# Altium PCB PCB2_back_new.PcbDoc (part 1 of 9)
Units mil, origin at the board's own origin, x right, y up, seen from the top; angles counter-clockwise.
Board outline 6299 x 3937 mil, 4 copper layers (TopLayer, GROUND, VCC, BottomLayer); 253 components, 421 nets, 2085 pads, 712 vias.
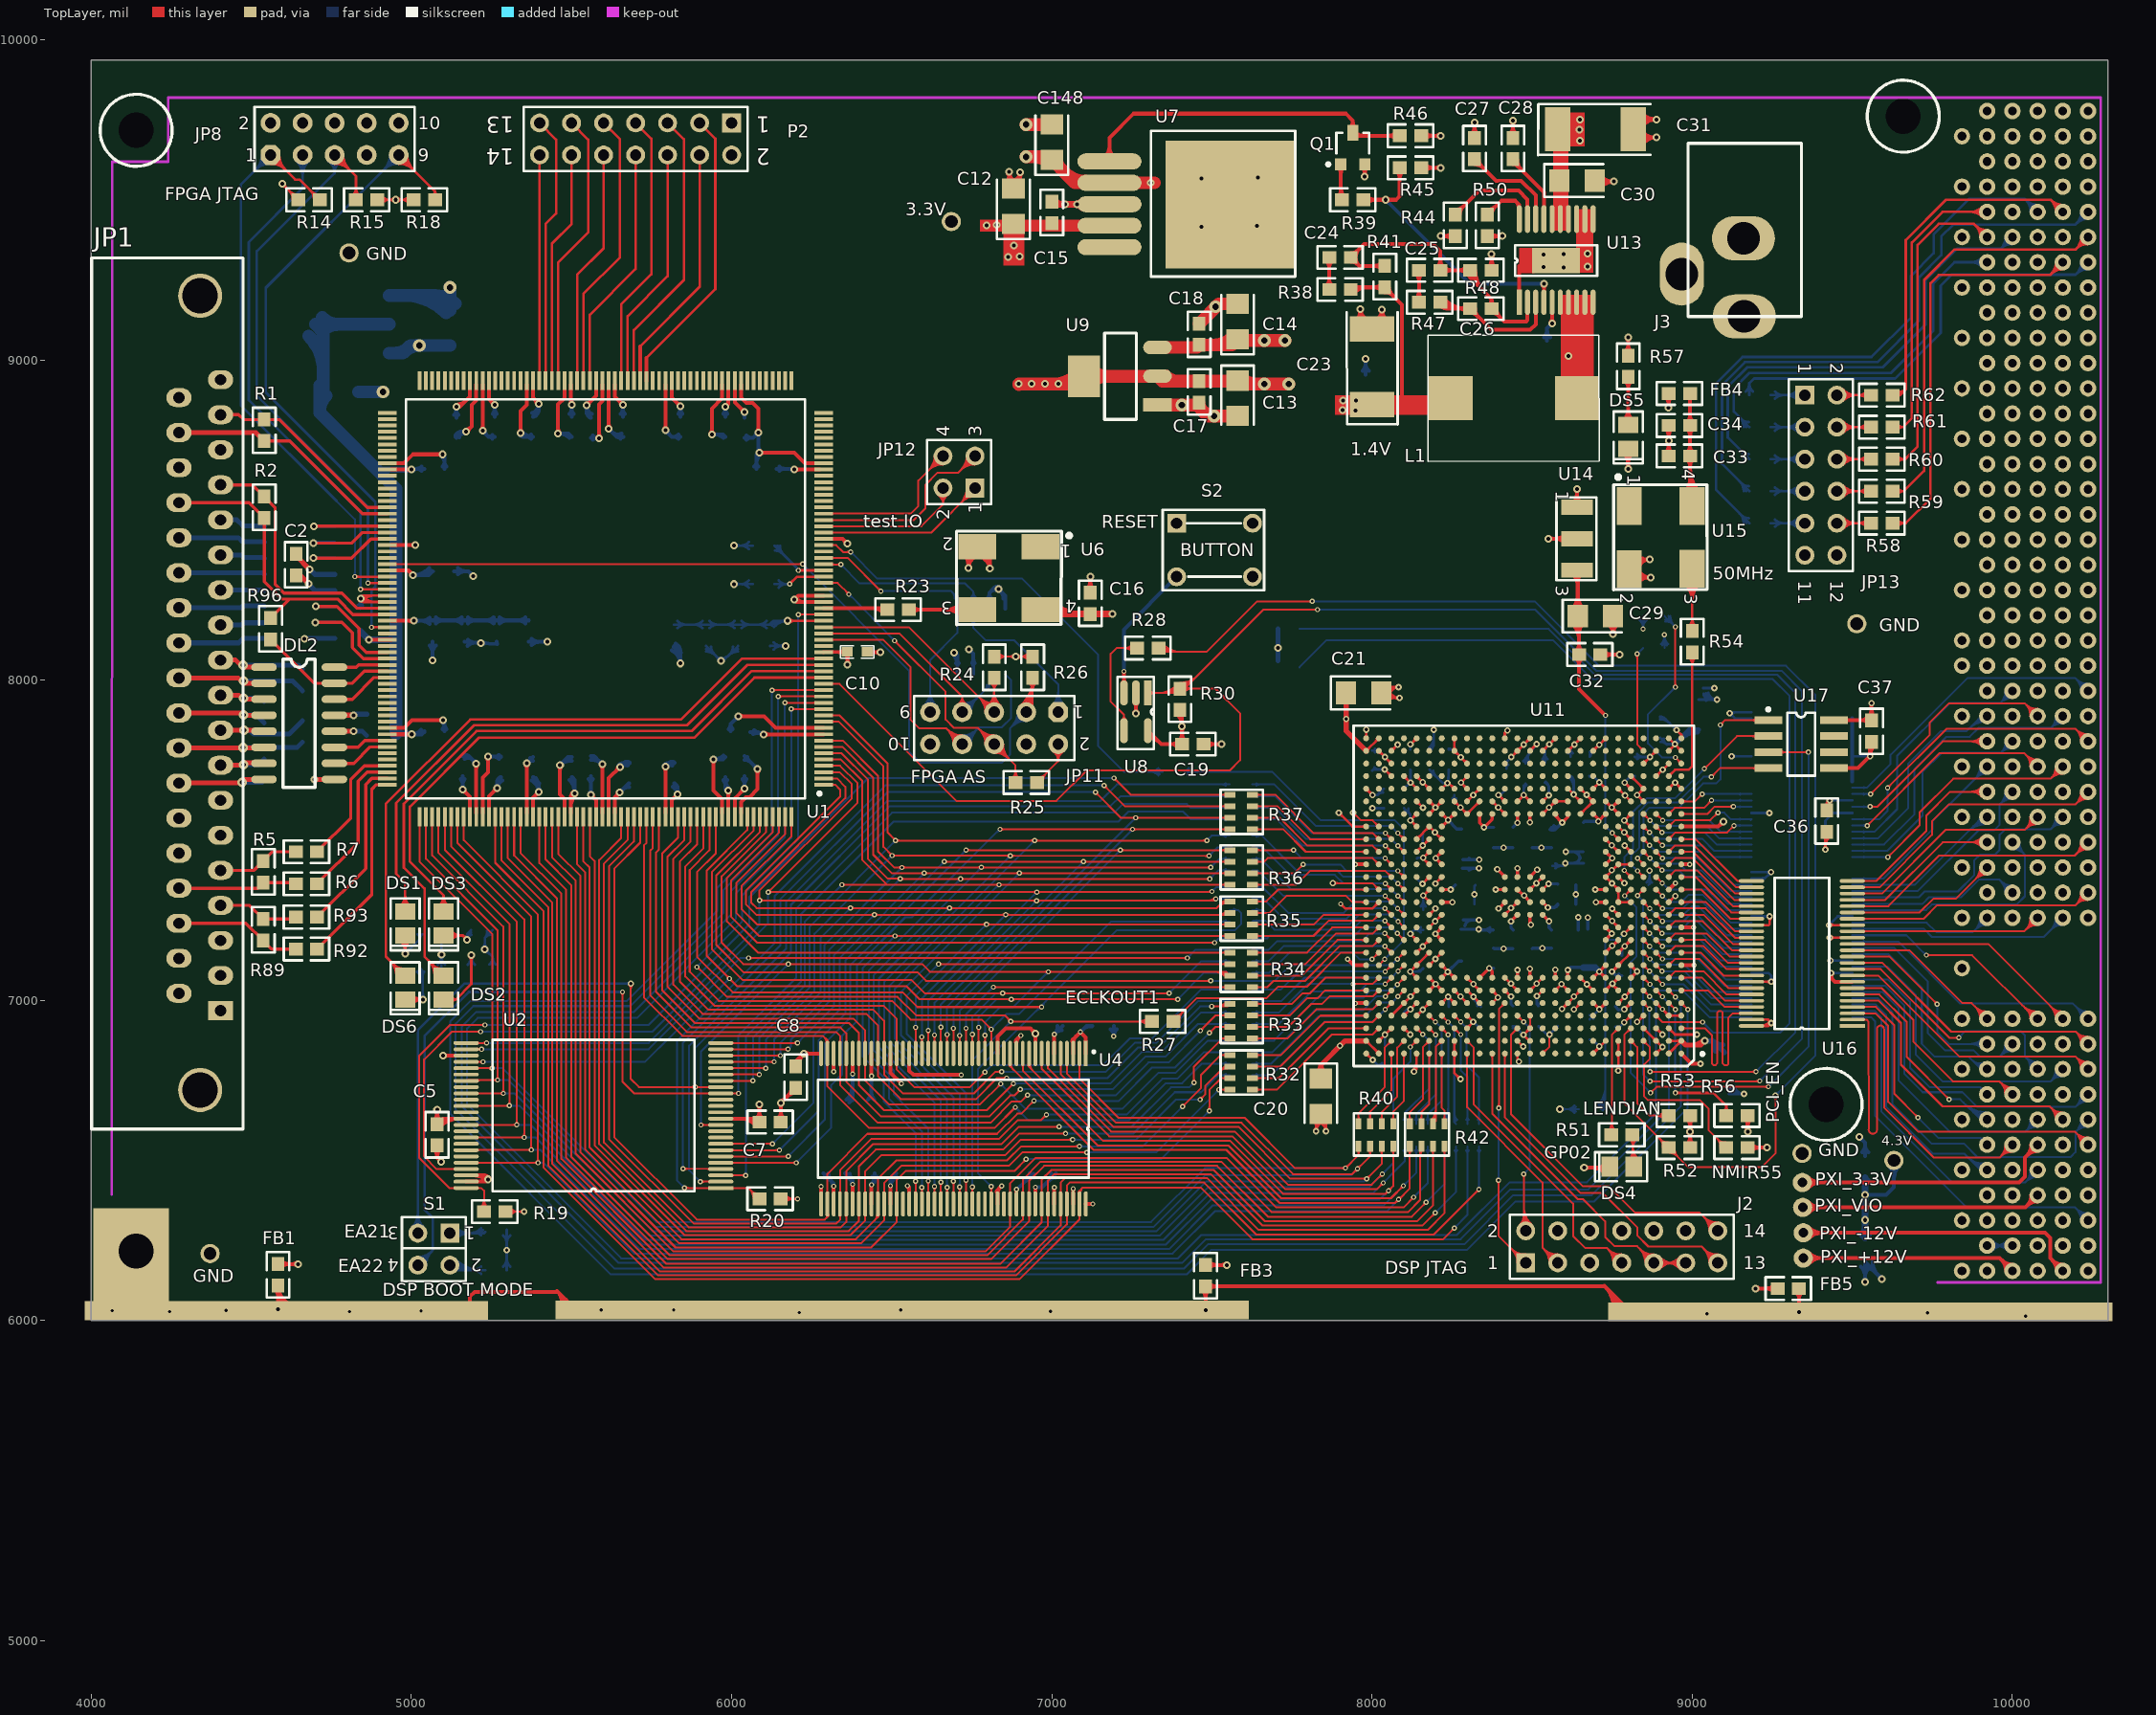
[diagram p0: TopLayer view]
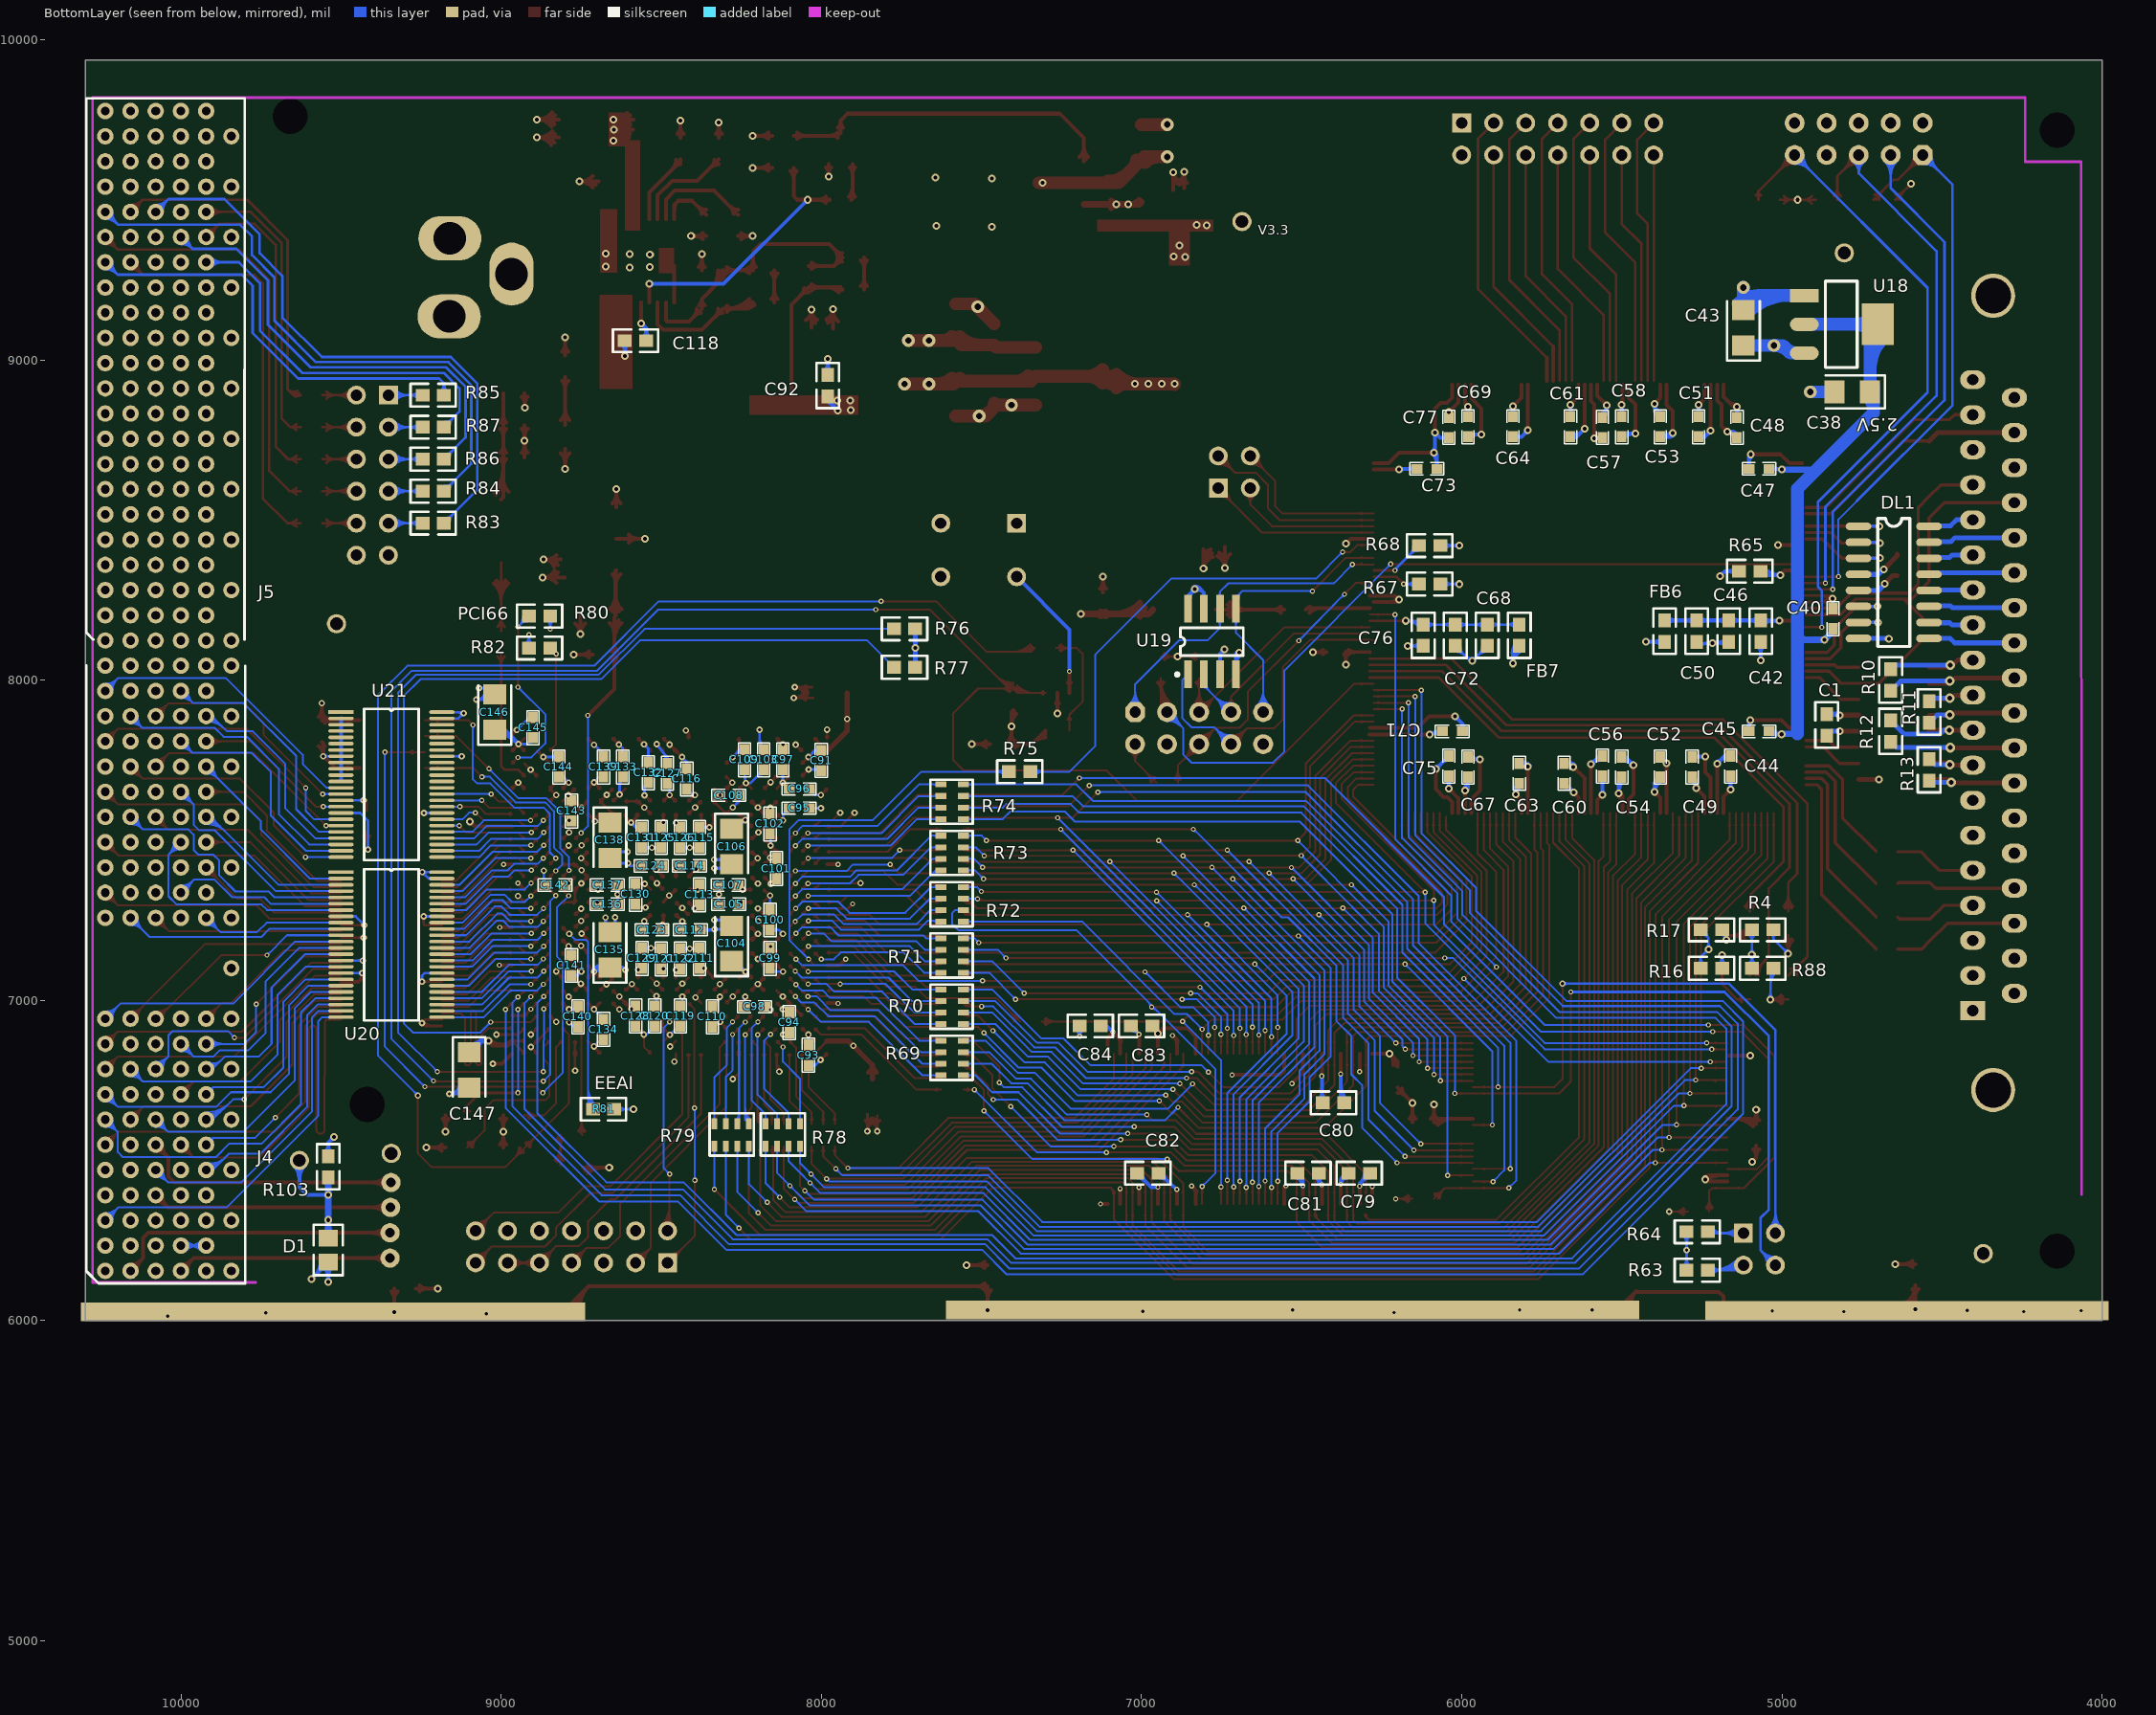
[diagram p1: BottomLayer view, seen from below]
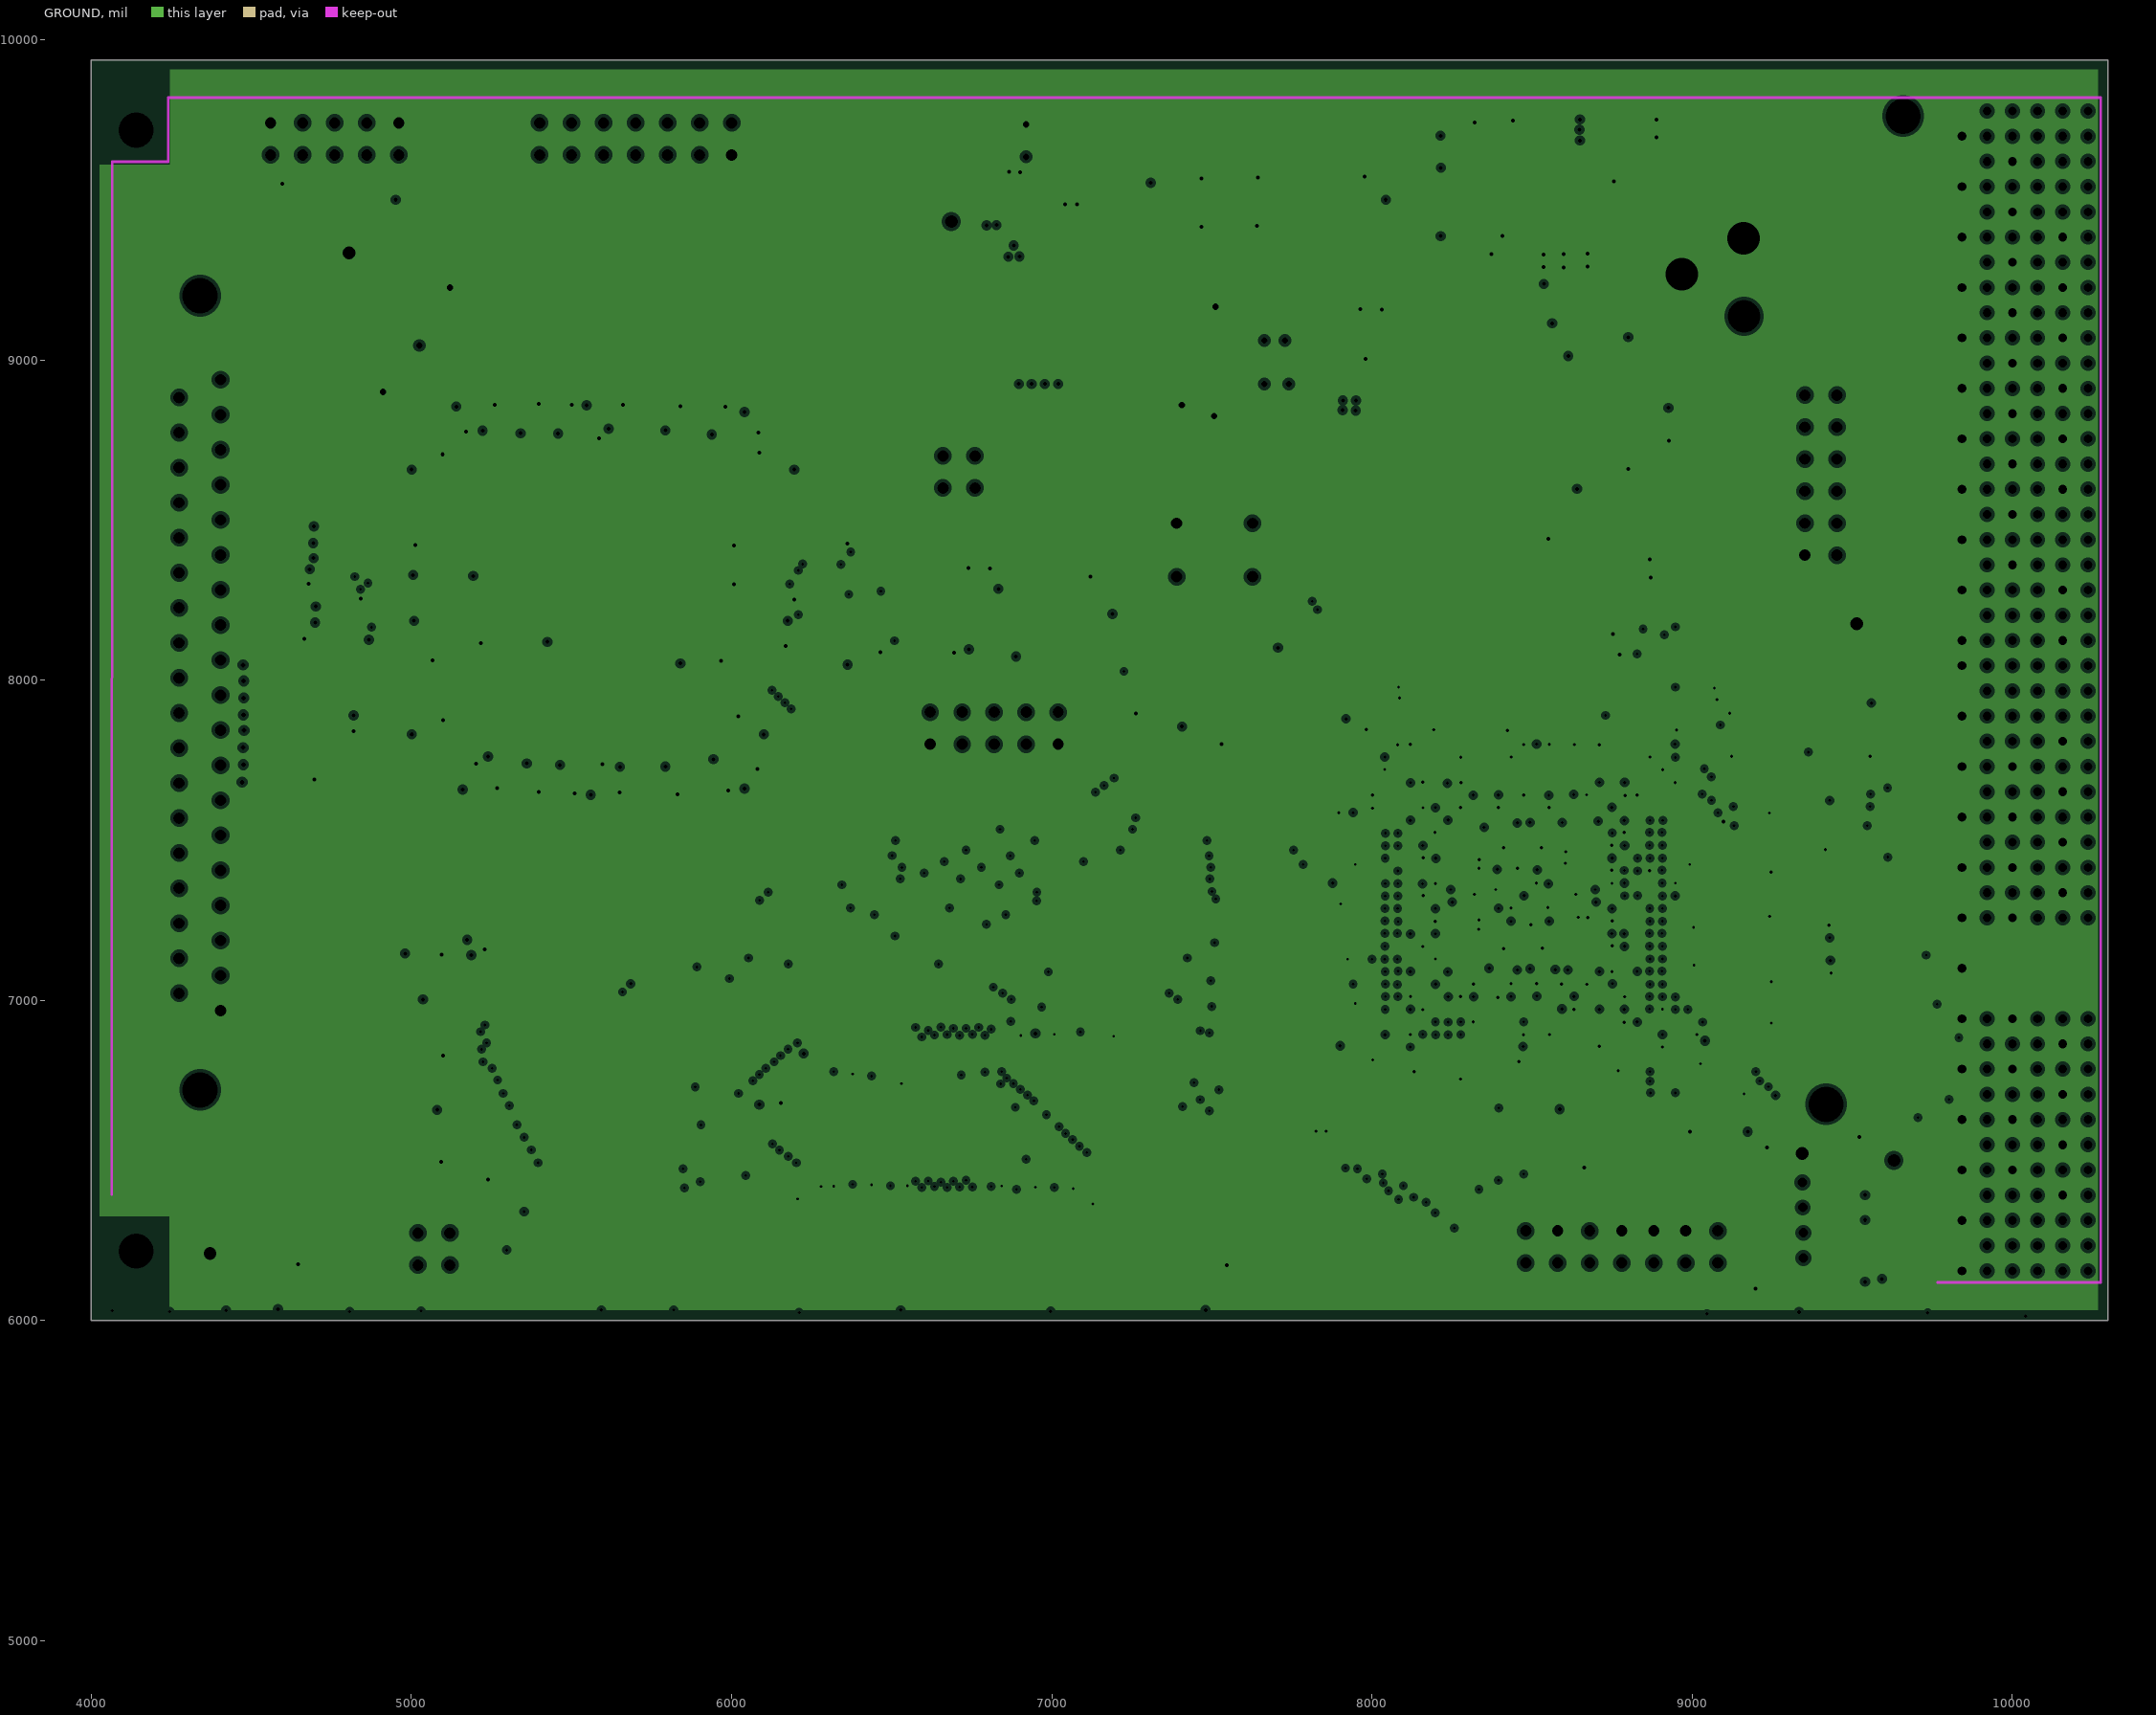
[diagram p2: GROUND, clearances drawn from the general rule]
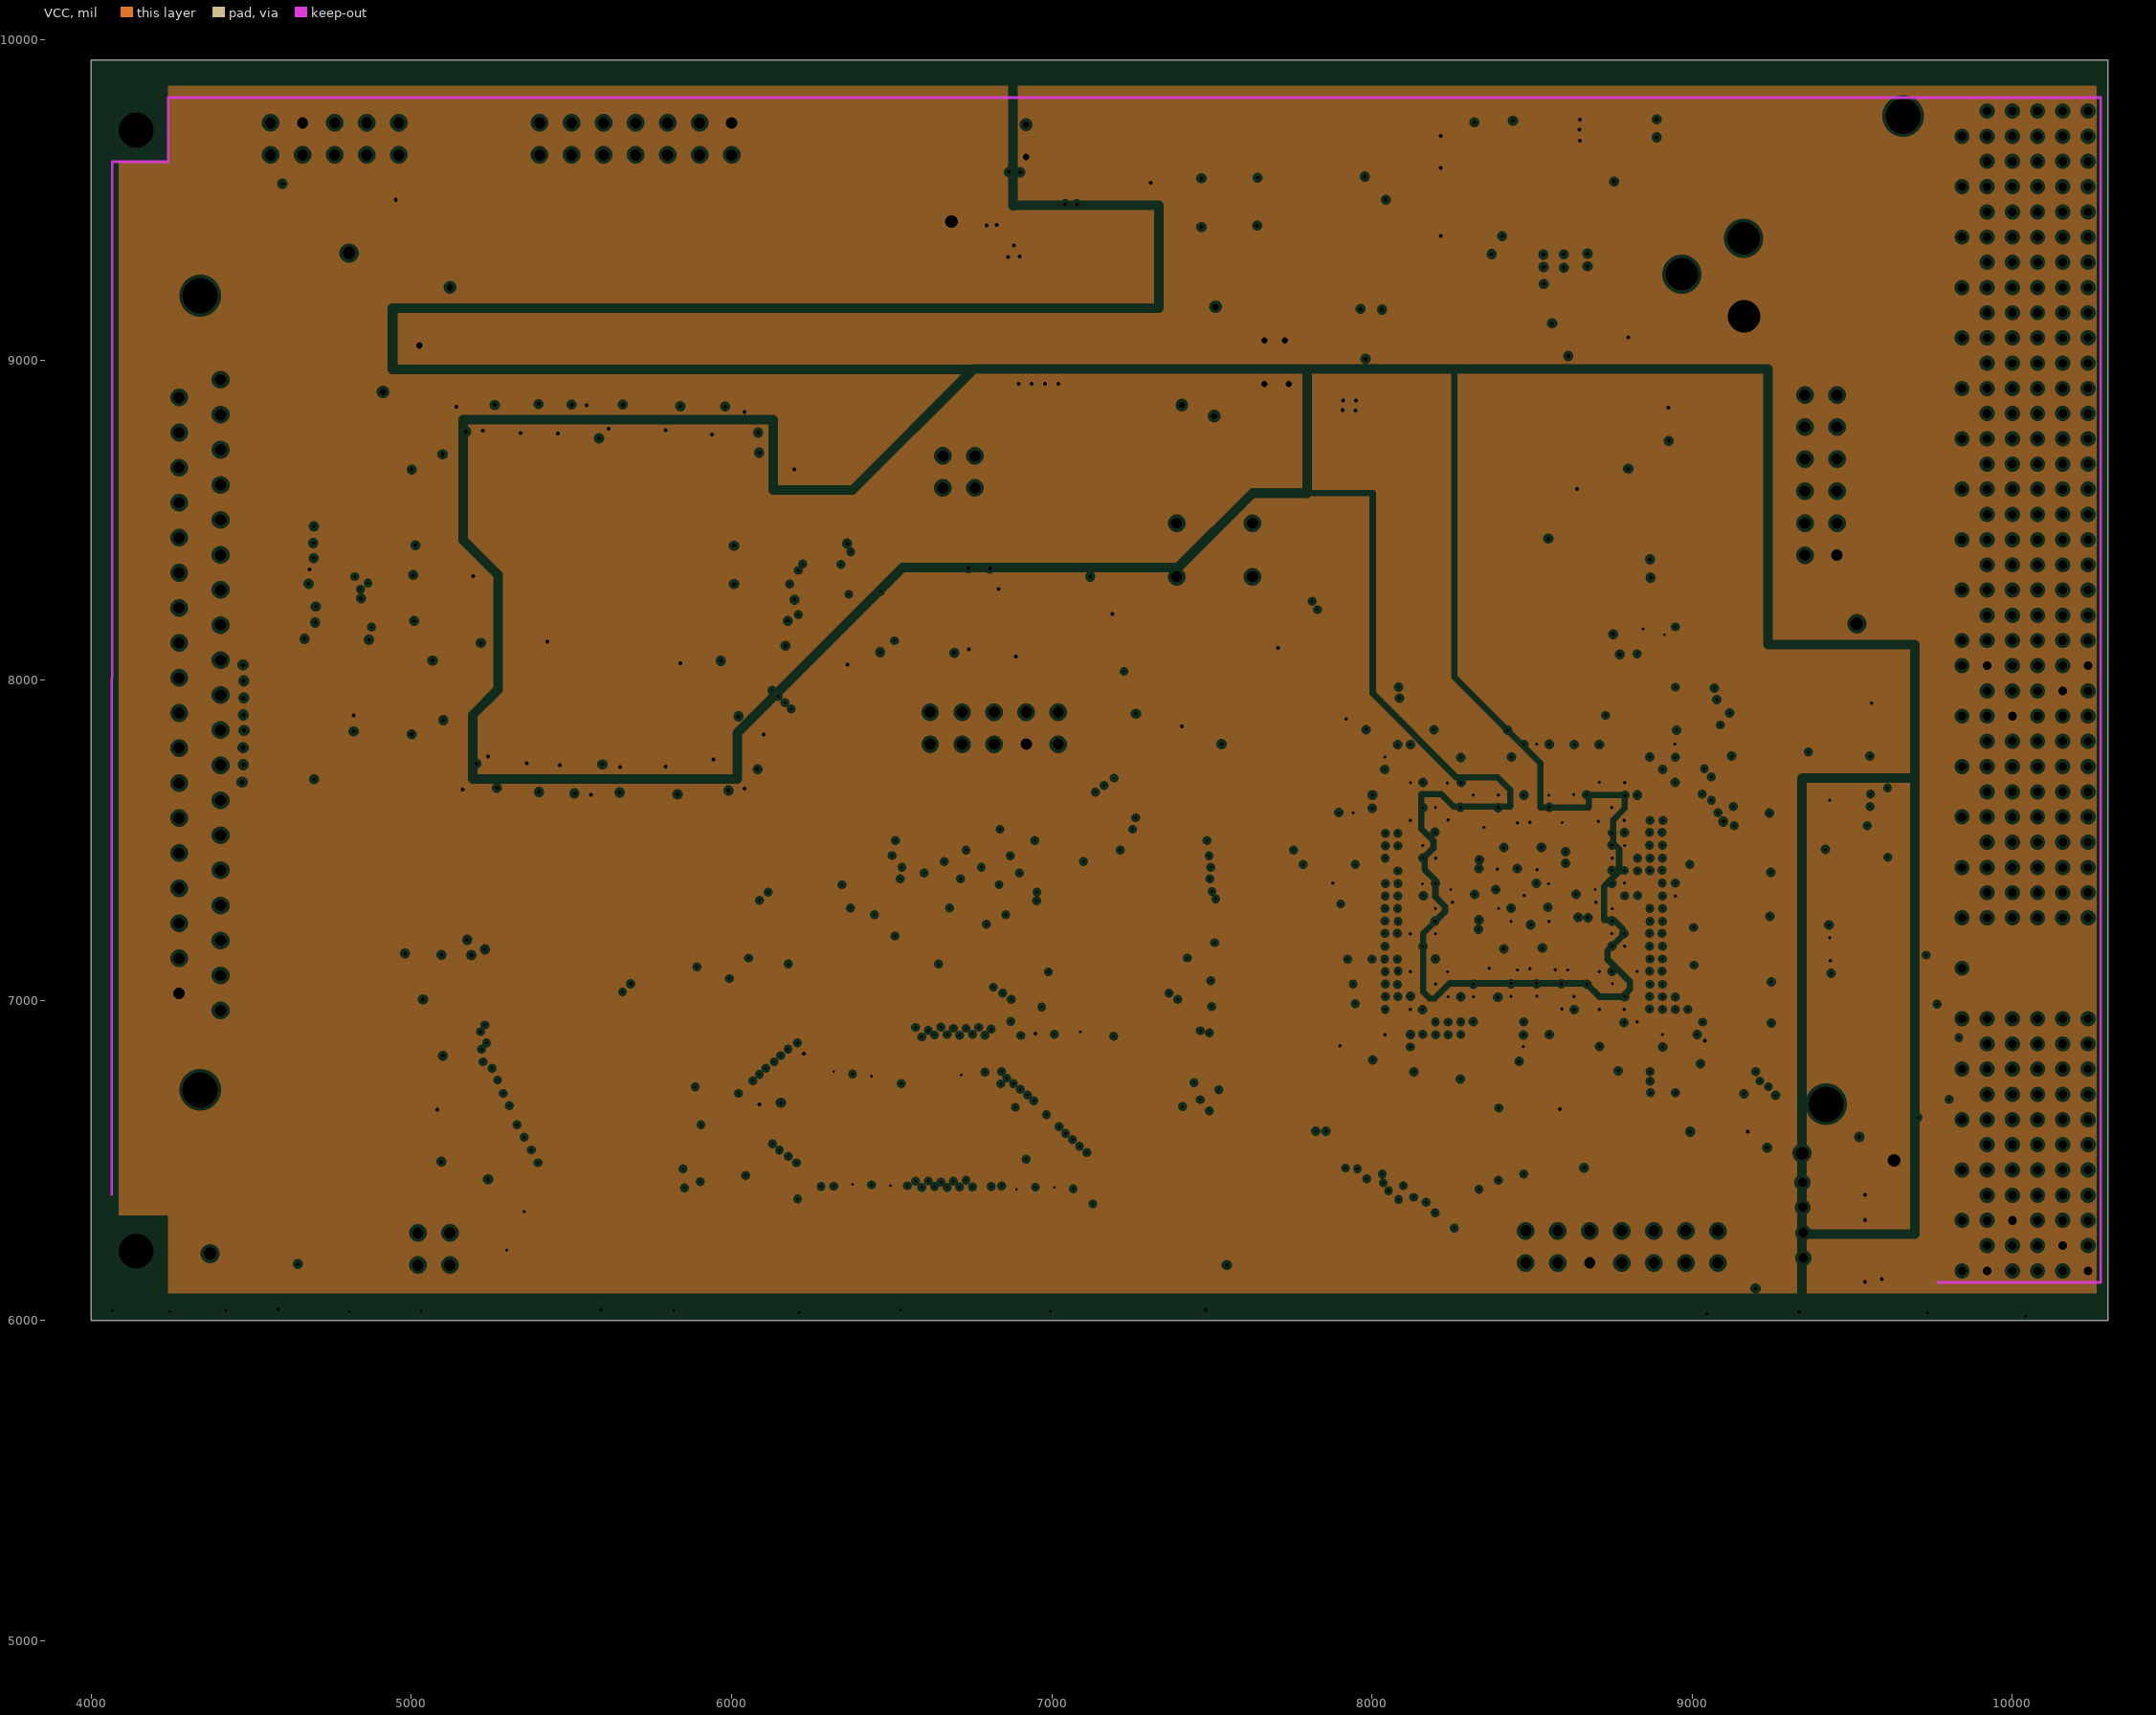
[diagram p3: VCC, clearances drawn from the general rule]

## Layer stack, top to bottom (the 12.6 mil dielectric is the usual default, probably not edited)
TopLayer: signal copper 1.4
Dielectric: core 12.6, FR-4, Dk 4.8
GROUND: plane copper 1.4, net GND
Dielectric: prepreg 12.6, FR-4, Dk 4.8
VCC: plane copper 1.4, net (Multiple Nets)
Dielectric: core 12.6, FR-4, Dk 4.8
BottomLayer: signal copper 1.4

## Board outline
4000,6000 10299,6000 10299,9937 4000,9937

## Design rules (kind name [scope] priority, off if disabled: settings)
Clearance [All] p1: gap=6
ComponentClearance ComponentClearance_1 [All] p1: gap=10 collisioncheckmode=3 verticalgap=10 showdistances=FALSE
FabricationTestPointUsage TestPointUsage_1 [All] p1: valid=0 allowmultiple=FALSE
FabricationTestpoint Testpoint_1 [All] p1: side=3 testpointundercomponent=TRUE minsize=40 maxsize=100 preferedsize=60 minholesize=20 maxholesize=40 preferedholesize=32 testpointgrid=1 allowsidetop=TRUE allowsidebottom=TRUE usegrid=TRUE gridtolerance=0.01
HoleSize HoleSize_1 [All] p1: absolutevalues=TRUE maxlimit=100 minlimit=1 maxpercent=80.000 minpercent=20.000
LayerPairs LayerPairs_1 [All] p1: enforce=TRUE
PasteMaskExpansion PasteMaskExpansion_1 [All] p1: expansion=0
PlaneClearance PlaneClearance_1 [All] p1: clearance=10
PlaneConnect [All] p1: planeconnectstyle=Relief reliefexpansion=15 reliefentries=4 reliefconductorwidth=30 reliefairgap=10
PolygonConnect PolygonConnect_1 [All] p1: connectstyle=Relief reliefconductorwidth=30 reliefentries=4 polygonreliefangle="90 Angle"
RoutingPriority RoutingPriority_1 [All] p1: routingpriority=0
RoutingTopology RoutingTopology_1 [All] p1: topology=Shortest
RoutingVias [All] p1: holewidth=12 width=24 viastyle="Through Hole" minholewidth=8 minwidth=16 maxholewidth=28 maxwidth=50
ShortCircuit ShortCircuit_1 [All] p1: allowed=FALSE
SilkscreenOverComponentPads [All] p1: minsilkscreentomaskgap=10
SolderMaskExpansion SolderMaskExpansion_1 [All] p1: expansion=2
UnRoutedNet UnRoutedNet_1 [All] p1:
Width [All] p1: maxlimit=200 minlimit=6 preferedwidth=6
15 further rules are at their usual default settings.

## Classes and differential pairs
component class U_Sheet1_FPGA2: C1 C2 C16 C39 C41 DL1 DL2 DS1 DS2 DS3 DS6 FB1 FB3 FB5 JP1 JP2 JP8 JP10 JP11 JP12 L2 P2 R1 R2 R4 R5 R6 R7 R8 R9 R10 R11 R12 R13 R14 R15 R16 R17 R18 R23 R24 R25 R26 R65 R67 R68 R75 R88 R89 R90 R91 R92 R93 R94 R95 R96 R97 R98 R99 R100 R101 R102 U1 U6 U19 U22
component class U_Sheet2_DSP_EMIF: C5 C7 C8 C79 C80 C81 C82 C83 C84 J2 R19 R20 R27 R32 R33 R34 R35 R36 R37 R40 R42 R63 R64 R69 R70 R71 R72 R73 R74 R78 R79 S1 U2 U4
component class U_Sheet2_PXI: C36 D1 J4 J5 JP13 R56 R58 R59 R60 R61 R62 R83 R84 R85 R86 R87 R103 U16 U20 U21
component class U_Sheet3_power_clock: C10 C12 C13 C14 C15 C17 C18 C20 C21 C23 C24 C25 C26 C27 C28 C30 C31 C35 C38 C40 C42 C43 C44 C45 C46 C47 C48 C49 C50 C51 C52 C53 C54 C56 C57 C58 C60 C61 C63 C64 C67 C68 C69 C71 C72 C73 C75 C76 C77 C91 C92 C93 C94 C95 C96 C97 C98 C99 C100 C101 C102 C103 C104 C105 C106 C107 C108 C109 C110 C111 C112 C113 C114 C115 C116 C118 C119 C120 C121 C122 C123 C124 C125 C126 C127 C128 C129 C130 C131 C132 C133 C134 C135 C136 C137 C138 C139 C140 C141 C142 C143 C144 C145 C146 C147 C148 DS5 FB6 FB7 J3 JP4 L1 Q1 R38 R39 R41 R44 R45 R46 R47 R48 R50 R57 U7 U9 U13 U18
component class U_Sheet4_DSP2_videoport: C19 C29 C32 C33 C34 C37 DS4 FB4 R28 R30 R51 R52 R53 R54 R55 R76 R77 R80 R81 R82 R? S2 U8 U11 U14 U15 U17

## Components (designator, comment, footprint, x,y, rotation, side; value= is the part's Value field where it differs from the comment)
C1 "0.1uF" C1608-0603 4860,7860 r270 bottom
C2 "0.1uF" C1608-0603 4640,8360 r270 top
C5 "Cap" C1608-0603 5080,6580 r90 top
C7 "Cap" C1608-0603 6120,6620 r0 top
C8 "Cap" C1608-0603 6200,6760 r90 top
C10 "Cap" 0603 6361,8088 r0 top
C12 "Cap Pol1" CC3216-1206 6880,9480 r90 top
C13 "Cap Pol1" CC3216-1206 7580,8880 r270 top
C14 "Cap Pol1" CC3216-1206 7580,9120 r90 top
C15 "Cap" C1608-0603 7000,9460 r270 top
C16 "Cap" C1608-0603 7120,8240 r270 top
C17 "Cap" C1608-0603 7460,8900 r90 top
C18 "Cap" C1608-0603 7460,9080 r270 top
C19 "Cap" C1608-0603 7440,7800 r180 top
C20 "Cap Pol2" CC3216-1206 7840,6700 r270 top
C21 "Cap Pol2" CC3216-1206 7974,7960 r0 top
C23 "Cap Pol1" CC6032 8000,8860 r90 top
C24 "Cap" C1608-0603 7900,9320 r180 top
C25 "Cap" C1608-0603 8180,9280 r180 top
C26 "Cap" C1608-0603 8340,9160 r180 top
C27 "Cap" C1608-0603 8320,9660 r270 top
C28 "Cap" C1608-0603 8440,9660 r270 top
C29 "Cap Pol2" CC3216-1206 8697.68,8200 r0 top
C30 "Cap Pol2" CC3216-1206 8640,9560 r0 top
C31 "Cap Pol1" CC6032 8580,9720 r0 top
C32 "Cap" C1608-0603 8680,8080 r180 top
C33 "Cap" C1608-0603 8960,8700 r0 top
C34 "Cap" C1608-0603 8960,8795 r0 top
C36 "Cap" C1608-0603 9420,7560 r90 top
C37 "Cap" C1608-0603 9560,7840 r90 top
C38 "Cap Pol1" CC3216-1206 4780,8900 r0 bottom
C40 "Cap" 0603 4840,8160 r90 bottom
C42 "Cap" C1608-0603 5066,8153 r90 bottom
C43 "Cap Pol1" CC3216-1206 5120,9100 r90 bottom
C44 "Cap" 0603 5160,7700 r90 bottom
C45 "Cap" 0603 5040,7840 r0 bottom
C46 "Cap" C1608-0603 5166,8153 r90 bottom
C47 "Cap" 0603 5040,8660 r0 bottom
C48 "Cap" 0603 5140,8820 r270 bottom
C49 "Cap" 0603 5280,7760 r270 bottom
C50 "Cap Pol1" C1608-0603 5266,8153 r270 bottom
C51 "Cap" 0603 5260,8760 r90 bottom
C52 "Cap" 0603 5380,7760 r270 bottom
C53 "Cap" 0603 5380,8760 r90 bottom
C54 "Cap" 0603 5500,7760 r270 bottom
C56 "Cap" 0603 5560,7700 r90 bottom
C57 "Cap" 0603 5560,8820 r270 bottom
C58 "Cap" 0603 5500,8760 r90 bottom
C60 "Cap" 0603 5680,7740 r270 bottom
C61 "Cap" 0603 5660,8760 r90 bottom
C63 "Cap" 0603 5820,7740 r270 bottom
C64 "Cap" 0603 5840,8760 r90 bottom
C67 "Cap" 0603 5980,7760 r270 bottom
C68 "Cap" C1608-0603 5920,8140 r90 bottom
C69 "Cap" 0603 5980,8760 r90 bottom
C71 "Cap" 0603 6060,7840 r180 bottom
C72 "Cap Pol1" C1608-0603 6020,8140 r270 bottom
C73 "Cap" 0603 6140,8660 r180 bottom
C75 "Cap" 0603 6040,7700 r90 bottom
C76 "Cap" C1608-0603 6120,8140 r90 bottom
C77 "Cap" 0603 6040,8820 r270 bottom
C79 "Cap" C1608-0603 6320,6460 r0 bottom
C80 "Cap" C1608-0603 6400,6680 r0 bottom
C81 "Cap" C1608-0603 6480,6460 r0 bottom
C82 "Cap" C1608-0603 6980,6460 r180 bottom
C83 "Cap" C1608-0603 7000,6920 r180 bottom
C84 "Cap" C1608-0603 7160,6920 r180 bottom
C91 "Cap" 0603 8000,7780 r270 bottom
C92 "Cap" C1608-0603 7980,8920 r270 bottom
C93 "Cap" 0603 8040,6860 r270 bottom
C94 "Cap" 0603 8100,6962 r270 bottom
C95 "Cap" 0603 8100,7600 r180 bottom
C96 "Cap" 0603 8100,7660 r180 bottom
C97 "Cap" 0603 8120,7720 r90 bottom
C98 "Cap" 0603 8240,6980 r180 bottom
C99 "Cap" 0603 8160,7100 r90 bottom
C100 "Cap" 0603 8160,7220 r90 bottom
C101 "Cap" 0603 8140,7380 r90 bottom
C102 "Cap" 0603 8160,7520 r90 bottom
C103 "Cap" 0603 8180,7720 r90 bottom
C104 "Cap Pol2" CC3216-1206 8280,7177.69 r90 bottom
C105 "Cap" 0603 8320,7300 r180 bottom
C106 "Cap Pol2" CC3216-1206 8280,7480 r270 bottom
C107 "Cap" 0603 8260,7360 r0 bottom
C108 "Cap" 0603 8320,7640 r180 bottom
C109 "Cap" 0603 8240,7720 r90 bottom
C110 "Cap" 0603 8340,6980 r270 bottom
C111 "Cap" 0603 8380,7100 r90 bottom
C112 "Cap" 0603 8378,7220 r0 bottom
C113 "Cap" 0603 8380,7298 r90 bottom
C114 "Cap" 0603 8380,7420 r0 bottom
C115 "Cap" 0603 8380,7540 r270 bottom
C116 "Cap" 0603 8420,7660 r90 bottom
C118 "Cap" C1608-0603 8580,9060 r0 bottom
C119 "Cap" 0603 8440,6982 r270 bottom
C120 "Cap" 0603 8520,6982 r270 bottom
C121 "Cap" 0603 8500,7098 r90 bottom
C122 "Cap" 0603 8440,7098 r90 bottom
C123 "Cap" 0603 8560,7220 r180 bottom
C124 "Cap" 0603 8500,7420 r0 bottom
C125 "Cap" 0603 8500,7540 r270 bottom
C126 "Cap" 0603 8440,7540 r270 bottom
C127 "Cap" 0603 8480,7740 r270 bottom
C128 "Cap" 0603 8580,6982 r270 bottom
C129 "Cap" 0603 8560,7100 r90 bottom
C130 "Cap" 0603 8580,7300 r90 bottom
C131 "Cap" 0603 8560,7540 r270 bottom
C132 "Cap" 0603 8540,7680 r90 bottom
C133 "Cap" 0603 8620,7698 r90 bottom
C134 "Cap" 0603 8680,6940 r270 bottom
C135 "Cap Pol2" CC3216-1206 8660,7157.69 r90 bottom
C136 "Cap" 0603 8700,7300 r180 bottom
C137 "Cap" 0603 8700,7360 r180 bottom
C138 "Cap Pol2" CC3216-1206 8660,7500 r270 bottom
C139 "Cap" 0603 8680,7698 r90 bottom
C140 "Cap" 0603 8760,6980 r270 bottom
C141 "Cap" 0603 8780,7140 r270 bottom
C142 "Cap" 0603 8800,7360 r0 bottom
C143 "Cap" 0603 8780,7560 r90 bottom
C144 "Cap" 0603 8820,7698 r90 bottom
C145 "Cap" 0603 8900,7820 r90 bottom
C146 "Cap Pol2" CC3216-1206 9020,7900 r90 bottom
C147 "Cap Pol2" CC3216-1206 9100,6782.31 r270 bottom
C148 "Cap Pol1" CC3216-1206 7000,9680 r90 top
D1 "Diode" CR2012-0805 9540,6220 r90 bottom
DL1 "DS90LV047" SO-16 4760,8480 r180 bottom
DL2 "DS90LV048" SO-16 4540,8040 r0 top
DS1 "LED2" "SMD _LED" 4980,7240 r90 top
DS2 "LED2" "SMD _LED" 5100,7040 r90 top
DS3 "LED2" "SMD _LED" 5100,7240 r90 top
DS4 "LED3" "SMD _LED" 8780,6480 r0 top
DS5 "LED3" "SMD _LED" 8800,8760 r90 top
DS6 "LED2" "SMD _LED" 4980,7040 r90 top
FB1 "FB" C1608-0603 4583,6143 r90 top
FB3 "FB" C1608-0603 7480,6140 r90 top
FB4 "BLM18PG121SN1" C1608-0603 8960,8895 r0 top
FB5 "FB" C1608-0603 9300,6100 r180 top
FB6 "FB" C1608-0603 5366,8153 r90 bottom
FB7 "FB" C1608-0603 5820,8140 r90 bottom
J2 "Header 7X2 JTAG" HDR2X7 8480,6180 r0 top
J3 "PWP_CON" POWER 9160,9380 r0 top
J4 "352068-1" PCI2-H123 10039.37,7100.06 r270 bottom locked
J5 "352152-1" PCI2-H121 10039.37,8950.46 r270 bottom
JP1 "DB37" DB37 4340,6720 r90 top
JP8 "JTAG" HDR2X5 4560,9640 r0 top
JP11 "AS mode" HDR2X5 7020,7900 r180 top
JP12 "Header 2X2" HDR2X2 6760,8600 r90 top
JP13 "Header 6X2" HDR2X6 9352,8890 r270 top
L1 "Inductor Iron" L44.7uH 8640,8880 r180 top
P2 "Header 7X2" HDR2X7 6000,9740 r180 top
Q1 "QNPN3904" "SO-G3 for NPN" 7940,9660 r0 top
R1 "Res2" C1608-0603 4540,8780 r270 top (schematic designator R2)
R2 "Res2" C1608-0603 4540,8540 r270 top
R4 "Res2" C1608-0603 5060,7220 r0 bottom
R5 "Res2" C1608-0603 4537,7401 r270 top
R6 "Res2" C1608-0603 4672,7364 r0 top
R7 "Res2" C1608-0603 4672,7464 r0 top
R10 "" CR1608-0603 4660,8000 r270 bottom
R11 "" CR1608-0603 4540,7900 r270 bottom
R12 "" CR1608-0603 4660,7840 r270 bottom
R13 "" CR1608-0603 4540,7720 r270 bottom
R14 "Res2" C1608-0603 4680,9500 r0 top
R15 "Res2" C1608-0603 4860,9500 r0 top
R16 "Res2" C1608-0603 5220,7100 r0 bottom
R17 "Res2" C1608-0603 5220,7220 r0 bottom
R18 "Res2" C1608-0603 5040,9500 r180 top
R19 "Res1" CR1608-0603 5260,6340 r0 top
R20 "Res1" CR1608-0603 6120,6380 r180 top
R23 "Res2" C1608-0603 6520,8220 r180 top
R24 "Res2" C1608-0603 6820,8040 r90 top
R25 "Res2" C1608-0603 6920,7680 r180 top
R26 "Res2" C1608-0603 6940,8040 r90 top
R27 "Res1" CR1608-0603 7346,6934 r180 top
R28 "Res1" CR1608-0603 7300,8100 r0 top
R30 "Res1" CR1608-0603 7400,7940 r270 top
R32 "R0604_4" R0603_4 7626,6721 r180 top
R33 "R0604_4" R0603_4 7626,6881 r180 top
R34 "R0604_4" R0603_4 7626,7041 r180 top
R35 "R0604_4" R0603_4 7626,7201 r180 top
R36 "R0604_4" R0603_4 7626,7361 r180 top
R37 "R0604_4" R0603_4 7626,7534 r180 top
R38 "Res1" CR1608-0603 7900,9220 r0 top
R39 "Res3" CR1608-0603 7940,9500 r0 top
R40 "R0604_4" R0603_4 8066,6614 r270 top
R41 "Res1" CR1608-0603 8040,9260 r270 top
R42 "R0604_4" R0603_4 8226,6614 r270 top
R44 "Res1" CR1608-0603 8260,9420 r270 top
R45 "Res1" CR1608-0603 8120,9600 r180 top
R46 "Res3" CR1608-0603 8120,9700 r0 top
R47 "Res1" CR1608-0603 8180,9180 r0 top
R48 "Res1" CR1608-0603 8340,9280 r180 top
R50 "Res1" CR1608-0603 8360,9420 r90 top
R51 "Res1" CR1608-0603 8780,6580 r0 top
R52 "Res1" CR1608-0603 8960,6540 r180 top
R53 "Res1" CR1608-0603 8960,6640 r180 top
R54 "Res1" CR1608-0603 9000,8120 r270 top
R55 "Res1" CR1608-0603 9140,6540 r180 top
R56 "Res1" CR1608-0603 9140,6640 r0 top
R57 "Res2" CR1608-0603 8800,8980 r90 top
R58 "Res1" CR1608-0603 9592,8490 r180 top
R59 "Res1" CR1608-0603 9592,8590 r180 top
R60 "Res1" CR1608-0603 9592,8690 r180 top
R61 "Res1" CR1608-0603 9592,8790 r180 top
R62 "Res1" CR1608-0603 9592,8890 r180 top
R63 "Res1" CR1608-0603 5264,6157 r180 bottom
R64 "Res1" CR1608-0603 5264,6277 r180 bottom
R65 "Res2" C1608-0603 5100,8340 r0 bottom
R67 "Res2" C1608-0603 6100,8300 r0 bottom
R68 "Res2" C1608-0603 6100,8420 r0 bottom
R69 "R0604_4" R0603_4 7626,6874 r180 bottom
R70 "R0604_4" R0603_4 7626,7034 r180 bottom
R71 "R0604_4" R0603_4 7626,7194 r180 bottom
R72 "R0604_4" R0603_4 7626,7354 r180 bottom
R73 "R0604_4" R0603_4 7626,7514 r180 bottom
R74 "R0604_4" R0603_4 7626,7674 r180 bottom
R75 "Res1" CR1608-0603 7380,7714 r0 bottom
R76 "Res1" CR1608-0603 7740,8160 r0 bottom
R77 "Res1" CR1608-0603 7740,8040 r0 bottom
R78 "R0604_4" R0603_4 8066,6614 r270 bottom
R79 "R0604_4" R0603_4 8226,6614 r270 bottom
R80 "Res1" CR1608-0603 8880,8200 r180 bottom
R81 "Res1" C1608-0603 8680,6660 r180 bottom
R82 "Res1" CR1608-0603 8880,8100 r0 bottom
R83 "Res1" CR1608-0603 9212,8490 r180 bottom
R84 "Res1" CR1608-0603 9212,8590 r180 bottom
R85 "Res1" CR1608-0603 9212,8890 r180 bottom
R86 "Res1" CR1608-0603 9212,8690 r180 bottom
R87 "Res1" CR1608-0603 9212,8790 r180 bottom
R88 "Res2" C1608-0603 5060,7100 r0 bottom
R89 "Res2" C1608-0603 4537,7220 r270 top
R92 "Res2" C1608-0603 4672,7160 r0 top
R93 "Res2" C1608-0603 4672,7260 r0 top
R96 "Res2" C1608-0603 4560,8160 r270 top
R103 "Res2" C1608-0603 9540,6480 r90 bottom
S1 "SW DIP-2" HEADER2X2 5120,6273 r180 top
S2 "SW-PB" BUTTON 7540,8440 r270 top
U1 "EP1C12Q240C6" PQFP240 5606,8254 r180 top locked
U2 "Am29LV800B" TSOP48 5966,6414 r180 top locked
U4 "HY57V283220" TSOP86 7106,6834 r270 top locked
U6 "Oscillator   27MHz" OSC 6880,8220 r270 top
U7 "TPS75733" SOT23-5S 7180,9620 r0 top
U8 "TPS3823-33" DBV5 7300,7960 r270 top
U9 "AS1117-1.5V" LM1117 7080,9000 r180 top
U11 "TMS320DM642" GNZ548 8966,6834 r0 top
U13 "TPS54310" PWP20 8460,9180 r90 top
U14 "ACF451832" ACF451832 8640,8540 r270 top
U15 "Oscillator" OSC50MHz 9000,8460 r0 top
U16 "SN74CBT16210" SSOP48 9500,6920 r180 top
U17 "93C66B" SO-G8 9340,7800 r270 top
U18 "AS1117-1.5V" LM1117 4680,9060 r180 bottom
U19 "EPCS1SI8" SOIC8 6780,8120 r180 bottom
U20 "SN74CBT16210" SSOP48 9500,7400 r180 bottom
U21 "SN74CBT16210" SSOP48 9500,7900 r180 bottom

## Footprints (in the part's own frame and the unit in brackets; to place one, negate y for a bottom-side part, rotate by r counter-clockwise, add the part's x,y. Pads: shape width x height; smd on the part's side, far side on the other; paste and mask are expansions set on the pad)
0603 [mil] "for DSP"
  rect 35x30 smd: 1(0,0) 2(62.99,0)
  silkscreen extent -22,-19 84,19
ACF451832 [mm] "for ACF451832-333-T"
  rect 1.2x2.5 smd: 1(0,0) 2(2.5,0) 3(5,0)
  silkscreen extent -0.76,-1.63 5.79,1.55
BUTTON [mm]
  rect 1.5x1.5 hole 0.9: 1(-1.27,-3.81)
  round 1.5 hole 0.9: 2(2.98,-3.81) 3(2.98,2.2) 4(-1.27,2.2)
  silkscreen extent -2.34,-4.93 4.04,3.12
C1608-0603 [mm]
  rect 1.1x1 smd: 1(-0.85,0) 2(0.85,0)
  silkscreen extent -1.8,-0.9 1.8,0.9
CC3216-1206 [mm]
  rect 1.6x1.8 smd: 1(-1.4,0) 2(1.4,0)
  silkscreen extent -2.6,-1.3 2.1,1.3
CC6032 [mm] "for 100uF"
  rect 2x3.5 smd: 1(0,0) 2(6,0)
  silkscreen extent -1.56,-2.03 7.34,2.01
CR1608-0603 [mm]
  rect 1.1x1 smd: 1(-0.85,0) 2(0.85,0)
  silkscreen extent -1.8,-0.9 1.8,0.9
CR2012-0805 [mm]
  rect 1.3x1.5 smd: 1(-0.95,0) 2(0.95,0)
  silkscreen extent -2,-1.15 2,1.15
DB37 [mm]
  round 3.5 hole 2.8: 0(0,0) 0(63,0)
  rect 1.5x2 hole 0.9: 1(6.3,-1.62)
  oval 1.5x2 hole 0.9: 2(9.08,-1.62) 3(11.86,-1.62) 4(14.64,-1.62) 5(17.42,-1.62) 6(20.2,-1.62) 7(22.98,-1.62) 8(25.76,-1.62) 9(28.54,-1.62) 10(31.32,-1.62) 11(34.1,-1.62) 12(36.88,-1.62) 13(39.66,-1.62) 14(42.44,-1.62) 15(45.22,-1.62) 16(48,-1.62) 17(50.78,-1.62) 18(53.56,-1.62) 19(56.34,-1.62) 20(7.665,1.68) 21(10.445,1.68) 22(13.225,1.68) 23(16.005,1.68) 24(18.785,1.68) 25(21.565,1.68) 26(24.345,1.68) 27(27.125,1.68) 28(29.905,1.68) 29(32.685,1.68) 30(35.465,1.68) 31(38.245,1.68) 32(41.025,1.68) 33(43.805,1.68) 34(46.585,1.68) 35(49.365,1.68) 36(52.145,1.68) 37(54.925,1.68)
  silkscreen extent -3.1,-3.4 66,8.6
DBV5 [mm] "DBV5;DBV (R-PDSO-G5);PSO;for TPS3823-33"
  rect 2x0.6 smd: 1(0,0)
  oval 2x0.6 smd: 2(0,-0.95) 3(0,-1.9) 4(3,-1.9) 5(3,0)
  silkscreen extent -1.27,-2.41 4.45,0.48
GNZ548 [mm] "BGA;548 Balls;Body 27 x 27 mm;for DM642"
  round 0.47 smd: A1(0,0) A2(-1,0) A3(-2,0) A4(-3,0) A5(-4,0) A6(-5,0) A7(-6,0) A8(-7,0) A9(-8,0) A10(-9,0) A11(-10,0) A12(-11,0) A13(-12,0) A14(-13,0) A15(-14,0) A16(-15,0) A17(-16,0) A18(-17,0) A19(-18,0) A20(-19,0) A21(-20,0) A22(-21,0) A23(-22,0) A24(-23,0) A25(-24,0) A26(-25,0) AA1(0,20) AA2(-1,20) AA3(-2,20) AA4(-3,20) AA5(-4,20) AA6(-5,20) AA7(-6,20) AA8(-7,20) AA9(-8,20) AA10(-9,20) AA11(-10,20) AA12(-11,20) AA13(-12,20) AA14(-13,20) AA15(-14,20) AA16(-15,20) AA17(-16,20) AA18(-17,20) AA19(-18,20) AA20(-19,20) AA21(-20,20) AA22(-21,20) AA23(-22,20) AA24(-23,20) AA25(-24,20) AA26(-25,20) AB1(0,21) AB2(-1,21) AB3(-2,21) AB4(-3,21) AB5(-4,21) AB6(-5,21) AB7(-6,21) AB8(-7,21) AB9(-8,21) AB10(-9,21) AB11(-10,21) AB12(-11,21) AB13(-12,21) AB14(-13,21) AB15(-14,21) AB16(-15,21) AB17(-16,21) AB18(-17,21) AB19(-18,21) AB20(-19,21) AB21(-20,21) AB22(-21,21) AB23(-22,21) AB24(-23,21) AB25(-24,21) AB26(-25,21) AC1(0,22) AC2(-1,22) AC3(-2,22) AC4(-3,22) AC5(-4,22) AC6(-5,22) AC7(-6,22) AC8(-7,22) AC9(-8,22) AC10(-9,22) AC11(-10,22) AC12(-11,22) AC13(-12,22) AC14(-13,22) AC15(-14,22) AC16(-15,22) AC17(-16,22) AC18(-17,22) AC19(-18,22) AC20(-19,22) AC21(-20,22) AC22(-21,22) AC23(-22,22) AC24(-23,22) AC25(-24,22) AC26(-25,22) AD1(0,23) AD2(-1,23) AD3(-2,23) AD4(-3,23) AD5(-4,23) AD6(-5,23) AD7(-6,23) AD8(-7,23) AD9(-8,23) AD10(-9,23) AD11(-10,23) AD12(-11,23) AD13(-12,23) AD14(-13,23) AD15(-14,23) AD16(-15,23) AD17(-16,23) AD18(-17,23) AD19(-18,23) AD20(-19,23) AD21(-20,23) AD22(-21,23) AD23(-22,23) AD24(-23,23) AD25(-24,23) AD26(-25,23) AE1(0,24) AE2(-1,24) AE3(-2,24) AE4(-3,24) AE5(-4,24) AE6(-5,24) AE7(-6,24) AE8(-7,24) AE9(-8,24) AE10(-9,24) AE11(-10,24) AE12(-11,24) AE13(-12,24) AE14(-13,24) AE15(-14,24) AE16(-15,24) AE17(-16,24) AE18(-17,24) AE19(-18,24) AE20(-19,24) AE21(-20,24) AE22(-21,24) AE23(-22,24) AE24(-23,24) AE25(-24,24) AE26(-25,24) AF1(0,25) AF2(-1,25) AF3(-2,25) AF4(-3,25) AF5(-4,25) AF6(-5,25) AF7(-6,25) AF8(-7,25) AF9(-8,25) AF10(-9,25) AF11(-10,25) AF12(-11,25) AF13(-12,25) AF14(-13,25) AF15(-14,25) AF16(-15,25) AF17(-16,25) AF18(-17,25) AF19(-18,25) AF20(-19,25) AF21(-20,25) AF22(-21,25) AF23(-22,25) AF24(-23,25) AF25(-24,25) AF26(-25,25) B1(0,1) B2(-1,1) B3(-2,1) B4(-3,1) B5(-4,1) B6(-5,1) B7(-6,1) B8(-7,1) B9(-8,1) B10(-9,1) B11(-10,1) B12(-11,1) B13(-12,1) B14(-13,1) B15(-14,1) B16(-15,1) B17(-16,1) B18(-17,1) B19(-18,1) B20(-19,1) B21(-20,1) B22(-21,1) B23(-22,1) B24(-23,1) B25(-24,1) B26(-25,1) C1(0,2) C2(-1,2) C3(-2,2) C4(-3,2) C5(-4,2) C6(-5,2) C7(-6,2) C8(-7,2) C9(-8,2) C10(-9,2) C11(-10,2) C12(-11,2) C13(-12,2) C14(-13,2) C15(-14,2) C16(-15,2) C17(-16,2) C18(-17,2) C19(-18,2) C20(-19,2) C21(-20,2) C22(-21,2) C23(-22,2) C24(-23,2) C25(-24,2) C26(-25,2) D1(0,3) D2(-1,3) D3(-2,3) D4(-3,3) D5(-4,3) D6(-5,3) D7(-6,3) D8(-7,3) D9(-8,3) D10(-9,3) D11(-10,3) D12(-11,3) D13(-12,3) D14(-13,3) D15(-14,3) D16(-15,3) D17(-16,3) D18(-17,3) D19(-18,3) D20(-19,3) D21(-20,3) D22(-21,3) D23(-22,3) D24(-23,3) D25(-24,3) D26(-25,3) E1(0,4) E2(-1,4) E3(-2,4) E4(-3,4) E5(-4,4) E6(-5,4) E7(-6,4) E8(-7,4) E9(-8,4) E10(-9,4) E11(-10,4) E12(-11,4) E13(-12,4) E14(-13,4) E15(-14,4) E16(-15,4) E17(-16,4) E18(-17,4) E19(-18,4) E20(-19,4) E21(-20,4) E22(-21,4) E23(-22,4) E24(-23,4) E25(-24,4) E26(-25,4) F1(0,5) F2(-1,5) F3(-2,5) F4(-3,5) F5(-4,5) F6(-5,5) F7(-6,5) F8(-7,5) F9(-8,5) F10(-9,5) F11(-10,5) F12(-11,5) F13(-12,5) F14(-13,5) F15(-14,5) F16(-15,5) F17(-16,5) F18(-17,5) F19(-18,5) F20(-19,5) F21(-20,5) F22(-21,5) F23(-22,5) F24(-23,5) F25(-24,5) F26(-25,5) G1(0,6) G2(-1,6) G3(-2,6) G4(-3,6) G5(-4,6) G6(-5,6) G7(-6,6) G8(-7,6) G9(-8,6) G10(-9,6) G11(-10,6) G12(-11,6) G13(-12,6) G14(-13,6) G15(-14,6) G16(-15,6) G17(-16,6) G18(-17,6) G19(-18,6) G20(-19,6) G21(-20,6) G22(-21,6) G23(-22,6) G24(-23,6) G25(-24,6) G26(-25,6) H1(0,7) H2(-1,7) H3(-2,7) H4(-3,7) H5(-4,7) H6(-5,7) H7(-6,7) H20(-19,7) H21(-20,7) H22(-21,7) H23(-22,7) H24(-23,7) H25(-24,7) H26(-25,7) J1(0,8) J2(-1,8) J3(-2,8) J4(-3,8) J5(-4,8) J6(-5,8) J7(-6,8) J20(-19,8) J21(-20,8) J22(-21,8) J23(-22,8) J24(-23,8) J25(-24,8) J26(-25,8) K1(0,9) K2(-1,9) K3(-2,9) K4(-3,9) K5(-4,9) K6(-5,9) K7(-6,9) K20(-19,9) K21(-20,9) K22(-21,9) K23(-22,9) K24(-23,9) K25(-24,9) K26(-25,9) L1(0,10) L2(-1,10) L3(-2,10) L4(-3,10) L5(-4,10) L6(-5,10) L7(-6,10) L20(-19,10) L21(-20,10) L22(-21,10) L23(-22,10) L24(-23,10) L25(-24,10) L26(-25,10) M1(0,11) M2(-1,11) M3(-2,11) M4(-3,11) M5(-4,11) M6(-5,11) M7(-6,11) M12(-11,11) M13(-12,11) M14(-13,11) M15(-14,11) M20(-19,11) M21(-20,11) M22(-21,11) M23(-22,11) M24(-23,11) M25(-24,11) M26(-25,11) N1(0,12) N2(-1,12) N3(-2,12) N4(-3,12) N5(-4,12) N6(-5,12) N7(-6,12) N12(-11,12) N13(-12,12) N14(-13,12) N15(-14,12) N20(-19,12) N21(-20,12) N22(-21,12) N23(-22,12) N24(-23,12) N25(-24,12) N26(-25,12) P1(0,13) P2(-1,13) P3(-2,13) P4(-3,13) P5(-4,13) P6(-5,13) P7(-6,13) P12(-11,13) P13(-12,13) P14(-13,13) P15(-14,13) P20(-19,13) P21(-20,13) P22(-21,13) P23(-22,13) P24(-23,13) P25(-24,13) P26(-25,13) R1(0,14) R2(-1,14) R3(-2,14) R4(-3,14) R5(-4,14) R6(-5,14) R7(-6,14) R12(-11,14) R13(-12,14) R14(-13,14) R15(-14,14) R20(-19,14) R21(-20,14) R22(-21,14) R23(-22,14) R24(-23,14) R25(-24,14) R26(-25,14) T1(0,15) T2(-1,15) T3(-2,15) T4(-3,15) T5(-4,15) T6(-5,15) T7(-6,15) T20(-19,15) T21(-20,15) T22(-21,15) T23(-22,15) T24(-23,15) T25(-24,15) T26(-25,15) U1(0,16) U2(-1,16) U3(-2,16) U4(-3,16) U5(-4,16) U6(-5,16) U7(-6,16) U20(-19,16) U21(-20,16) U22(-21,16) U23(-22,16) U24(-23,16) U25(-24,16) U26(-25,16) V1(0,17) V2(-1,17) V3(-2,17) V4(-3,17) V5(-4,17) V6(-5,17) V7(-6,17) V20(-19,17) V21(-20,17) V22(-21,17) V23(-22,17) V24(-23,17) V25(-24,17) V26(-25,17) W1(0,18) W2(-1,18) W3(-2,18) W4(-3,18) W5(-4,18) W6(-5,18) W7(-6,18) W20(-19,18) W21(-20,18) W22(-21,18) W23(-22,18) W24(-23,18) W25(-24,18) W26(-25,18) Y1(0,19) Y2(-1,19) Y3(-2,19) Y4(-3,19) Y5(-4,19) Y6(-5,19) Y7(-6,19) Y8(-7,19) Y9(-8,19) Y10(-9,19) Y11(-10,19) Y12(-11,19) Y13(-12,19) Y14(-13,19) Y15(-14,19) Y16(-15,19) Y17(-16,19) Y18(-17,19) Y19(-18,19) Y20(-19,19) Y21(-20,19) Y22(-21,19) Y23(-22,19) Y24(-23,19) Y25(-24,19) Y26(-25,19)
  silkscreen extent -26,-1.02 1.8,26
HDR2X2 [mm] "Connector; Header; 2x2 Position"
  rect 1.5x1.5 hole 0.9: 1(0,0)
  round 1.5 hole 0.9: 2(0,2.54) 3(2.54,0) 4(2.54,2.54)
  silkscreen extent -1.27,-1.27 3.81,3.81
HDR2X5 [mil]
  oct 62x62 hole 35: 1(0,0)
  round 62 hole 35: 2(0,100) 3(100,0) 4(100,100) 5(200,0) 6(200,100) 7(300,0) 8(300,100) 9(400,0) 10(400,100)
  silkscreen extent -50,-50 450,150
HDR2X6 [mm] "Connector; Header; 6x2 Position"
  rect 1.5x1.5 hole 0.9: 1(0,0)
  round 1.5 hole 0.9: 2(0,2.54) 3(2.54,0) 4(2.54,2.54) 5(5.08,0) 6(5.08,2.54) 7(7.62,0) 8(7.62,2.54) 9(10.16,0) 10(10.16,2.54) 11(12.7,0) 12(12.7,2.54)
  silkscreen extent -1.27,-1.27 13.97,3.81
HDR2X7 [mm] "Connector; Header; 7x2 Position"
  rect 1.5x1.5 hole 0.9: 1(0,0)
  round 1.5 hole 0.9: 2(0,2.54) 3(2.54,0) 4(2.54,2.54) 5(5.08,0) 6(5.08,2.54) 7(7.62,0) 8(7.62,2.54) 9(10.16,0) 10(10.16,2.54) 11(12.7,0) 12(12.7,2.54) 13(15.24,0) 14(15.24,2.54)
  silkscreen extent -1.27,-1.27 16.51,3.81
HEADER2X2 [mm]
  rect 1.5x1.5 hole 0.9: 1(0,0)
  round 1.5 hole 0.9: 2(0,2.54) 3(2.54,0) 4(2.54,2.54)
  silkscreen extent -1.27,-1.27 3.81,3.81
L44.7uH [mm] "for L4"
  rect 3.5x3.5 smd: 1(0,0) 2(10,0)
  silkscreen extent -1.78,-5 11.81,5
LM1117 [mil]
  rect 90x42 smd: 1(-250,141)
  oval 90x42 smd: 2(-250,51) 3(-250,-39)
  rect 100x130 smd: 2(-20,51)
  silkscreen extent -184,-84 -85,186
OSC [mm]
  rect 2x3 smd: 1(-5,2.134) 2(-5,-2.87) 3(0,-2.866) 4(0,2.134)
  silkscreen extent -6.22,-4.52 1.19,4.48
OSC50MHz [mm] "for 50MHz"
  rect 2x3 smd: 1(-5,2.134) 2(-5,-2.87) 3(0,-2.866) 4(0,2.134)
  silkscreen extent -6.22,-4.52 1.19,4.48
PCI2-H121 [mm]
  round 1.3 hole 0.7: A1(21,-5) A2(19,-5) A3(17,-5) A4(15,-5) A5(13,-5) A6(11,-5) A7(9,-5) A8(7,-5) A9(5,-5) A10(3,-5) A11(1,-5) A12(-1,-5) A13(-3,-5) A14(-5,-5) A15(-7,-5) A16(-9,-5) A17(-11,-5) A18(-13,-5) A19(-15,-5) A20(-17,-5) A21(-19,-5) A22(-21,-5) B1(21,-3) B2(19,-3) B3(17,-3) B4(15,-3) B5(13,-3) B6(11,-3) B7(9,-3) B8(7,-3) B9(5,-3) B10(3,-3) B11(1,-3) B12(-1,-3) B13(-3,-3) B14(-5,-3) B15(-7,-3) B16(-9,-3) B17(-11,-3) B18(-13,-3) B19(-15,-3) B20(-17,-3) B21(-19,-3) B22(-21,-3) C1(21,-1) C2(19,-1) C3(17,-1) C4(15,-1) C5(13,-1) C6(11,-1) C7(9,-1) C8(7,-1) C9(5,-1) C10(3,-1) C11(1,-1) C12(-1,-1) C13(-3,-1) C14(-5,-1) C15(-7,-1) C16(-9,-1) C17(-11,-1) C18(-13,-1) C19(-15,-1) C20(-17,-1) C21(-19,-1) C22(-21,-1) D1(21,1) D2(19,1) D3(17,1) D4(15,1) D5(13,1) D6(11,1) D7(9,1) D8(7,1) D9(5,1) D10(3,1) D11(1,1) D12(-1,1) D13(-3,1) D14(-5,1) D15(-7,1) D16(-9,1) D17(-11,1) D18(-13,1) D19(-15,1) D20(-17,1) D21(-19,1) D22(-21,1) E1(21,3) E2(19,3) E3(17,3) E4(15,3) E5(13,3) E6(11,3) E7(9,3) E8(7,3) E9(5,3) E10(3,3) E11(1,3) E12(-1,3) E13(-3,3) E14(-5,3) E15(-7,3) E16(-9,3) E17(-11,3) E18(-13,3) E19(-15,3) E20(-17,3) E21(-19,3) E22(-21,3) F1(21,5) F3(17,5) F5(13,5) F7(9,5) F9(5,5) F11(1,5) F13(-3,5) F15(-7,5) F17(-11,5) F19(-15,5) F21(-19,5)
  silkscreen extent -22,-6.5 20.93,6.05
PCI2-H123 [mm]
  round 1.3 hole 0.7: A1(24,-5) A2(22,-5) A3(20,-5) A4(18,-5) A5(16,-5) A6(14,-5) A7(12,-5) A8(10,-5) A9(8,-5) A10(6,-5) A11(4,-5) A15(-4,-5) A16(-6,-5) A17(-8,-5) A18(-10,-5) A19(-12,-5) A20(-14,-5) A21(-16,-5) A22(-18,-5) A23(-20,-5) A24(-22,-5) A25(-24,-5) B1(24,-3) B2(22,-3) B3(20,-3) B4(18,-3) B5(16,-3) B6(14,-3) B7(12,-3) B8(10,-3) B9(8,-3) B10(6,-3) B11(4,-3) B15(-4,-3) B16(-6,-3) B17(-8,-3) B18(-10,-3) B19(-12,-3) B20(-14,-3) B21(-16,-3) B22(-18,-3) B23(-20,-3) B24(-22,-3) B25(-24,-3) C1(24,-1) C2(22,-1) C3(20,-1) C4(18,-1) C5(16,-1) C6(14,-1) C7(12,-1) C8(10,-1) C9(8,-1) C10(6,-1) C11(4,-1) C15(-4,-1) C16(-6,-1) C17(-8,-1) C18(-10,-1) C19(-12,-1) C20(-14,-1) C21(-16,-1) C22(-18,-1) C23(-20,-1) C24(-22,-1) C25(-24,-1) D1(24,1) D2(22,1) D3(20,1) D4(18,1) D5(16,1) D6(14,1) D7(12,1) D8(10,1) D9(8,1) D10(6,1) D11(4,1) D15(-4,1) D16(-6,1) D17(-8,1) D18(-10,1) D19(-12,1) D20(-14,1) D21(-16,1) D22(-18,1) D23(-20,1) D24(-22,1) D25(-24,1) E1(24,3) E2(22,3) E3(20,3) E4(18,3) E5(16,3) E6(14,3) E7(12,3) E8(10,3) E9(8,3) E10(6,3) E11(4,3) E15(-4,3) E16(-6,3) E17(-8,3) E18(-10,3) E19(-12,3) E20(-14,3) E21(-16,3) E22(-18,3) E23(-20,3) E24(-22,3) E25(-24,3) F1(24,5) F3(20,5) F5(16,5) F7(12,5) F9(8,5) F11(4,5) F13(0,5) F15(-4,5) F17(-8,5) F19(-12,5) F21(-16,5) F23(-20,5) F25(-24,5)
  silkscreen extent -24.03,-6.5 25,6.1
POWER [mil]
  oval 197x138 hole 102: 1(2.16,-244.32) 2(0.16,-0.32)
  oval 138x197 hole 102: 3(-192.84,-112.32)
  silkscreen extent -173,-244 181,297
PQFP240 [mm] "byTX chaned for cyclone FPGA"
  rect 1.5x0.3 smd: 1(-17.3,14.75) 2(-17.3,14.25) 3(-17.3,13.75) 4(-17.3,13.25) 5(-17.3,12.75) 6(-17.3,12.25) 7(-17.3,11.75) 8(-17.3,11.25) 9(-17.3,10.75) 10(-17.3,10.25) 11(-17.3,9.75) 12(-17.3,9.25) 13(-17.3,8.75) 14(-17.3,8.25) 15(-17.3,7.75) 16(-17.3,7.25) 17(-17.3,6.75) 18(-17.3,6.25) 19(-17.3,5.75) 20(-17.3,5.25) 21(-17.3,4.75) 22(-17.3,4.25) 23(-17.3,3.75) 24(-17.3,3.25) 25(-17.3,2.75) 26(-17.3,2.25) 27(-17.3,1.75) 28(-17.3,1.25) 29(-17.3,0.75) 30(-17.3,0.25) 31(-17.3,-0.25) 32(-17.3,-0.75) 33(-17.3,-1.25) 34(-17.3,-1.75) 35(-17.3,-2.25) 36(-17.3,-2.75) 37(-17.3,-3.25) 38(-17.3,-3.75) 39(-17.3,-4.25) 40(-17.3,-4.75) 41(-17.3,-5.25) 42(-17.3,-5.75) 43(-17.3,-6.25) 44(-17.3,-6.75) 45(-17.3,-7.25) 46(-17.3,-7.75) 47(-17.3,-8.25) 48(-17.3,-8.75) 49(-17.3,-9.25) 50(-17.3,-9.75) 51(-17.3,-10.25) 52(-17.3,-10.75) 53(-17.3,-11.25) 54(-17.3,-11.75) 55(-17.3,-12.25) 56(-17.3,-12.75) 57(-17.3,-13.25) 58(-17.3,-13.75) 59(-17.3,-14.25) 60(-17.3,-14.75) 121(17.3,-14.75) 122(17.3,-14.25) 123(17.3,-13.75) 124(17.3,-13.25) 125(17.3,-12.75) 126(17.3,-12.25) 127(17.3,-11.75) 128(17.3,-11.25) 129(17.3,-10.75) 130(17.3,-10.25) 131(17.3,-9.75) 132(17.3,-9.25) 133(17.3,-8.75) 134(17.3,-8.25) 135(17.3,-7.75) 136(17.3,-7.25) 137(17.3,-6.75) 138(17.3,-6.25) 139(17.3,-5.75) 140(17.3,-5.25) 141(17.3,-4.75) 142(17.3,-4.25) 143(17.3,-3.75) 144(17.3,-3.25) 145(17.3,-2.75) 146(17.3,-2.25) 147(17.3,-1.75) 148(17.3,-1.25) 149(17.3,-0.75) 150(17.3,-0.25) 151(17.3,0.25) 152(17.3,0.75) 153(17.3,1.25) 154(17.3,1.75) 155(17.3,2.25) 156(17.3,2.75) 157(17.3,3.25) 158(17.3,3.75) 159(17.3,4.25) 160(17.3,4.75) 161(17.3,5.25) 162(17.3,5.75) 163(17.3,6.25) 164(17.3,6.75) 165(17.3,7.25) 166(17.3,7.75) 167(17.3,8.25) 168(17.3,8.75) 169(17.3,9.25) 170(17.3,9.75) 171(17.3,10.25) 172(17.3,10.75) 173(17.3,11.25) 174(17.3,11.75) 175(17.3,12.25) 176(17.3,12.75) 177(17.3,13.25) 178(17.3,13.75) 179(17.3,14.25) 180(17.3,14.75)
  rect 0.3x1.5 smd: 61(-14.75,-17.3) 62(-14.25,-17.3) 63(-13.75,-17.3) 64(-13.25,-17.3) 65(-12.75,-17.3) 66(-12.25,-17.3) 67(-11.75,-17.3) 68(-11.25,-17.3) 69(-10.75,-17.3) 70(-10.25,-17.3) 71(-9.75,-17.3) 72(-9.25,-17.3) 73(-8.75,-17.3) 74(-8.25,-17.3) 75(-7.75,-17.3) 76(-7.25,-17.3) 77(-6.75,-17.3) 78(-6.25,-17.3) 79(-5.75,-17.3) 80(-5.25,-17.3) 81(-4.75,-17.3) 82(-4.25,-17.3) 83(-3.75,-17.3) 84(-3.25,-17.3) 85(-2.75,-17.3) 86(-2.25,-17.3) 87(-1.75,-17.3) 88(-1.25,-17.3) 89(-0.75,-17.3) 90(-0.25,-17.3) 91(0.25,-17.3) 92(0.75,-17.3) 93(1.25,-17.3) 94(1.75,-17.3) 95(2.25,-17.3) 96(2.75,-17.3) 97(3.25,-17.3) 98(3.75,-17.3) 99(4.25,-17.3) 100(4.75,-17.3) 101(5.25,-17.3) 102(5.75,-17.3) 103(6.25,-17.3) 104(6.75,-17.3) 105(7.25,-17.3) 106(7.75,-17.3) 107(8.25,-17.3) 108(8.75,-17.3) 109(9.25,-17.3) 110(9.75,-17.3) 111(10.25,-17.3) 112(10.75,-17.3) 113(11.25,-17.3) 114(11.75,-17.3) 115(12.25,-17.3) 116(12.75,-17.3) 117(13.25,-17.3) 118(13.75,-17.3) 119(14.25,-17.3) 120(14.75,-17.3) 181(14.75,17.3) 182(14.25,17.3) 183(13.75,17.3) 184(13.25,17.3) 185(12.75,17.3) 186(12.25,17.3) 187(11.75,17.3) 188(11.25,17.3) 189(10.75,17.3) 190(10.25,17.3) 191(9.75,17.3) 192(9.25,17.3) 193(8.75,17.3) 194(8.25,17.3) 195(7.75,17.3) 196(7.25,17.3) 197(6.75,17.3) 198(6.25,17.3) 199(5.75,17.3) 200(5.25,17.3) 201(4.75,17.3) 202(4.25,17.3) 203(3.75,17.3) 204(3.25,17.3) 205(2.75,17.3) 206(2.25,17.3) 207(1.75,17.3) 208(1.25,17.3) 209(0.75,17.3) 210(0.25,17.3) 211(-0.25,17.3) 212(-0.75,17.3) 213(-1.25,17.3) 214(-1.75,17.3) 215(-2.25,17.3) 216(-2.75,17.3) 217(-3.25,17.3) 218(-3.75,17.3) 219(-4.25,17.3) 220(-4.75,17.3) 221(-5.25,17.3) 222(-5.75,17.3) 223(-6.25,17.3) 224(-6.75,17.3) 225(-7.25,17.3) 226(-7.75,17.3) 227(-8.25,17.3) 228(-8.75,17.3) 229(-9.25,17.3) 230(-9.75,17.3) 231(-10.25,17.3) 232(-10.75,17.3) 233(-11.25,17.3) 234(-11.75,17.3) 235(-12.25,17.3) 236(-12.75,17.3) 237(-13.25,17.3) 238(-13.75,17.3) 239(-14.25,17.3) 240(-14.75,17.3)
  silkscreen extent -17.1,-15.83 15.83,15.83
PWP20 [mm] "PWP20;PSO;PWP (R-PDSO-G**);for TPS54310"
  rect 2x0.4 smd: 1(0,0)
  rect 2.032x3.81 smd: 1(3.302,-2.921)
  oval 2x0.4 smd: 2(0,-0.65) 3(0,-1.3) 4(0,-1.95) 5(0,-2.6) 6(0,-3.25) 7(0,-3.9) 8(0,-4.55) 9(0,-5.2) 10(0,-5.85)
  oval 2.2x0.4 smd: 11(6.6,-5.85) 12(6.6,-5.2) 13(6.6,-4.55) 14(6.6,-3.9) 15(6.6,-3.25) 16(6.6,-2.6) 17(6.6,-1.95) 18(6.6,-1.3) 19(6.6,-0.65) 20(6.6,0)
  silkscreen extent 2.08,-6.18 4.51,0.33
R0603_4 [mil] "for ResPackX4____OK!"
  rect 35x18 smd: 1(0,0) 2(0,-36) 3(0,-72) 4(0,-108) 5(70.16,-108) 6(70.16,-72) 7(70.16,-36) 8(70.16,0)
  silkscreen extent -33,-123 99,15
"SMD _LED" [mm]
  rect 1.3x1.6 smd: 1(0.95,0) 2(-0.95,0)
  silkscreen extent -2.13,-1.15 2,1.15
SO-16 [mil]
  oval 80x24 smd: 1(-0.7,0.1) 2(-0.7,-49.9) 3(-0.7,-99.9) 4(-0.7,-149.9) 5(-0.7,-199.9) 6(-0.7,-249.9) 7(-0.7,-299.9) 8(-0.7,-349.9) 9(219.3,-349.9) 10(219.3,-299.9) 11(219.3,-249.9) 12(219.3,-199.9) 13(219.3,-149.9) 14(219.3,-99.9) 15(219.3,-49.9) 16(219.3,0.1)
  silkscreen extent 59,-375 159,25
"SO-G3 for NPN" [mm]
  rect 0.9x1.27 smd: 1(0,1.25)
  rect 0.9x0.95 smd: 2(-0.95,-1.25) 3(0.95,-1.25)
  silkscreen extent -2.07,-1.37 1.3,1.25
SO-G8 [mm]
  rect 0.6x2.2 smd: 1(-1.905,-2.6) 2(-0.635,-2.6) 3(0.635,-2.6) 4(1.905,-2.6) 5(1.905,2.6) 6(0.635,2.6) 7(-0.635,2.6) 8(-1.905,2.6)
  silkscreen extent -2.88,-2.72 2.5,1.1
SOIC8 [mm] "8-Pin Small-Outline Integrated Circuit (SOIC)"
  rect 0.6x2.2 smd: 1(-1.905,-2.6) 2(-0.635,-2.6) 3(0.635,-2.6) 4(1.905,-2.6) 5(1.905,2.6) 6(0.635,2.6) 7(-0.635,2.6) 8(-1.905,2.6)
  silkscreen extent -2.88,-2.72 2.5,1.1
SOT23-5S [mil] "for TPS75733"
  oval 200x50 smd: 1(0,0) 2(0,-67) 3(0,-134) 4(0,-201) 5(0,-268)
  rect 400x400 smd: 3(375,-135)
  silkscreen extent 130,-360 580,95
SSOP48 [mm]
  rect 2x0.28 smd: 1(0,0)
  oval 2x0.28 smd: 2(0,-0.5) 3(0,-1) 4(0,-1.5) 5(0,-2) 6(0,-2.5) 7(0,-3) 8(0,-3.5) 9(0,-4) 10(0,-4.5) 11(0,-5) 12(0,-5.5) 13(0,-6) 14(0,-6.5) 15(0,-7) 16(0,-7.5) 17(0,-8) 18(0,-8.5) 19(0,-9) 20(0,-9.5) 21(0,-10) 22(0,-10.5) 23(0,-11) 24(0,-11.5) 25(8,-11.5) 26(8,-11) 27(8,-10.5) 28(8,-10) 29(8,-9.5) 30(8,-9) 31(8,-8.5) 32(8,-8) 33(8,-7.5) 34(8,-7) 35(8,-6.5) 36(8,-6) 37(8,-5.5) 38(8,-5) 39(8,-4.5) 40(8,-4) 41(8,-3.5) 42(8,-3) 43(8,-2.5) 44(8,-2) 45(8,-1.5) 46(8,-1) 47(8,-0.5) 48(8,0)
  silkscreen extent 1.84,-11.75 6.16,0.25
TSOP48 [mm] "for Am29LV800B"
  rect 2x0.3 smd: 1(0,0)
  oval 2x0.3 smd: 2(0,-0.5) 3(0,-1) 4(0,-1.5) 5(0,-2) 6(0,-2.5) 7(0,-3) 8(0,-3.5) 9(0,-4) 10(0,-4.5) 11(0,-5) 12(0,-5.5) 13(0,-6) 14(0,-6.5) 15(0,-7) 16(0,-7.5) 17(0,-8) 18(0,-8.5) 19(0,-9) 20(0,-9.5) 21(0,-10) 22(0,-10.5) 23(0,-11) 24(0,-11.5) 25(20.2,-11.5) 26(20.2,-11) 27(20.2,-10.5) 28(20.2,-10) 29(20.2,-9.5) 30(20.2,-9) 31(20.2,-8.5) 32(20.2,-8) 33(20.2,-7.5) 34(20.2,-7) 35(20.2,-6.5) 36(20.2,-6) 37(20.2,-5.5) 38(20.2,-5) 39(20.2,-4.5) 40(20.2,-4) 41(20.2,-3.5) 42(20.2,-3) 43(20.2,-2.5) 44(20.2,-2) 45(20.2,-1.5) 46(20.2,-1) 47(20.2,-0.5) 48(20.2,0)
  silkscreen extent 2.08,-11.75 18.12,0.25
TSOP86 [mm] "TSOP;43*2;for HY57V283220"
  rect 2x0.3 smd: 1(0,0)
  oval 2x0.3 smd: 2(0,-0.5) 3(0,-1) 4(0,-1.5) 5(0,-2) 6(0,-2.5) 7(0,-3) 8(0,-3.5) 9(0,-4) 10(0,-4.5) 11(0,-5) 12(0,-5.5) 13(0,-6) 14(0,-6.5) 15(0,-7) 16(0,-7.5) 17(0,-8) 18(0,-8.5) 19(0,-9) 20(0,-9.5) 21(0,-10) 22(0,-10.5) 23(0,-11) 24(0,-11.5) 25(0,-12) 26(0,-12.5) 27(0,-13) 28(0,-13.5) 29(0,-14) 30(0,-14.5) 31(0,-15) 32(0,-15.5) 33(0,-16) 34(0,-16.5) 35(0,-17) 36(0,-17.5) 37(0,-18) 38(0,-18.5) 39(0,-19) 40(0,-19.5) 41(0,-20) 42(0,-20.5) 43(0,-21) 44(11.938,-21) 45(11.938,-20.5) 46(11.938,-20) 47(11.938,-19.5) 48(11.938,-19) 49(11.938,-18.5) 50(11.938,-18) 51(11.938,-17.5) 52(11.938,-17) 53(11.938,-16.5) 54(11.938,-16) 55(11.938,-15.5) 56(11.938,-15) 57(11.938,-14.5) 58(11.938,-14) 59(11.938,-13.5) 60(11.938,-13) 61(11.938,-12.5) 62(11.938,-12) 63(11.938,-11.5) 64(11.938,-11) 65(11.938,-10.5) 66(11.938,-10) 67(11.938,-9.5) 68(11.938,-9) 69(11.938,-8.5) 70(11.938,-8) 71(11.938,-7.5) 72(11.938,-7) 73(11.938,-6.5) 74(11.938,-6) 75(11.938,-5.5) 76(11.938,-5) 77(11.938,-4.5) 78(11.938,-4) 79(11.938,-3.5) 80(11.938,-3) 81(11.938,-2.5) 82(11.938,-2) 83(11.938,-1.5) 84(11.938,-1) 85(11.938,-0.5) 86(11.938,0)
  silkscreen extent -0.22,-21.25 9.85,0.73

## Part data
C1 C2: library part Cap, "Capacitor"
C5 C7 C8 C10 C15 C16 C17 C18 C19 C24 C25 C26 C27 C28 C32 C33 C34 C36 C37 C40 C42 C44 C45 C46 C47 C48 C49 C51 C52 C53 C54 C56 C57 C58 C60 C61 C63 C64 C67 C68 C69 C71 C73 C75 C76 C77 C79 C80 C81 C82 C83 C84 C91 C92 C93 C94 C95 C96 C97 C98 C99 C100 C101 C102 C103 C105 C107 C108 C109 C110 C111 C112 C113 C114 C115 C116 C118 C119 C120 C121 C122 C123 C124 C125 C126 C127 C128 C129 C130 C131 C132 C133 C134 C136 C137 C139 C140 C141 C142 C143 C144 C145: "Capacitor"
C12 C13 C14 C23 C31 C38 C43 C50 C72 C148: "Polarized Capacitor (Radial)"
C20 C21 C29 C30 C104 C106 C135 C138 C146 C147: "Polarized Capacitor (Axial)"
D1: "Default Diode"
DS1 DS2 DS3 DS6: "Typical RED, GREEN, YELLOW, AMBER GaAs LED"
DS4 DS5: "Typical BLUE SiC LED"
FB1 FB3 FB4 FB5 FB6 FB7: library part Inductor, "Inductor"
J2: library part "Header 7X2", "Header, 7-Pin, Dual row"
J4: "Z-Pack 2mm Hard Metric Type A 110 Position Female PCB Mount Connector"
J5: "Z-Pack 2mm Hard Metric Type B 110 Position Female Daughter Card Connector"
JP8 JP11: library part "Header 5X2", "Header, 5-Pin, Dual row"
JP12: "Header, 2-Pin, Dual row"
JP13: "Header, 6-Pin, Dual row"
L1: "Magnetic-Core Inductor"
P2: "Header, 7-Pin, Dual row"
Q1: library part QNPN, "NPN Bipolar Transistor"
R1 R2 R4 R5 R6 R7 R14 R15 R16 R17 R18 R19 R20 R23 R24 R25 R26 R27 R28 R30 R38 R39 R41 R44 R45 R46 R47 R48 R50 R51 R52 R53 R54 R55 R56 R57 R58 R59 R60 R61 R62 R63 R64 R65 R67 R68 R75 R76 R77 R80 R81 R82 R83 R84 R85 R86 R87 R88 R89 R92 R93 R96 R103: "Resistor"
R10 R11 R12 R13: library part Res1, "Resistor"
R32 R33 R34 R35 R36 R37 R40 R42 R69 R70 R71 R72 R73 R74 R78 R79: "Resistor Array - Parts"
S1: "DIP Switch"
S2: "Switch"
U1: "Cyclone Family, 1.5V FPGA, 173 I/O Pins, 2 x PLLs, Commercial Grade, Speed Grade 6"
U4: "by TX"
U6: library part Oscillator
U9 U18: library part "Volt Reg", "Voltage Regulator"
U14: library part "EMI filter"
U19: "EPCS1 Series, In-system programmable 3.3V configuration device, 8-Pin SOIC, 1-Megabit, Industrial Grade"

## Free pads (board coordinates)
  rect 236.22x314.96 smd: 0(4125,6193)
  round 60 hole 40: 0(9630,6500) 5(4371,6209) 6(4805,9334) 7(9514,8176) 8(9343,6522) 9(6686,9432)
  round 50 hole 110: 1(4140,9717) 1(9418,6675) 1(9659,9761) 2(4140,6217)
  round 60 hole 30: 1(9344,6431) 2(9345,6353) 3(9347,6274) 4(9347,6195)
  rect 1259.84x59.06 smd: 10(4609,6031)
  rect 1259.84x59.05 smd far side: 10(4609,6031)
  rect 2165.35x59.05 smd far side: 11(6528,6033)
  rect 2165.35x59.05 smd: 11(6532,6033)
  rect 1574.8x59.05 smd: 12(9525,6027)
  rect 1574.8x59.05 smd far side: 12(9525,6027)

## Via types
v1: diameter 16, hole 8, TopLayer to BottomLayer, 311 vias
v2: diameter 20, hole 10, TopLayer to BottomLayer, 202 vias
v3: diameter 24, hole 12, TopLayer to BottomLayer, 179 vias
v4: diameter 40, hole 20, TopLayer to BottomLayer, 12 vias
v5: diameter 30, hole 15, TopLayer to BottomLayer, 8 vias

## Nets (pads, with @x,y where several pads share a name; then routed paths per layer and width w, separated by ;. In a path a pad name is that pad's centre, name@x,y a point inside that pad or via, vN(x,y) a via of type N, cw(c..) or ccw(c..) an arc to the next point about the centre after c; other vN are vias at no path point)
1.4VPWRGD: R39.2 R45.2 U13.4 | length 1083.7
  TopLayer w12: R39.2@7973.46,9500 8075,9500 8086.54,9511.54 R45.2@8086.54,9600 ; R39.2@7985.11,9490.32 cw(c8008.47,9466.96) 8008.47,9500 cw(c8008.47,9533.04) R39.2@7985.11,9509.68 ; v3@8038.76,9495.76 ccw(c8028.51,9485.51) 8028.51,9500 ccw(c8028.51,9514.49) v3@8038.76,9504.24 ; v3@8047.24,9495.76 cw(c8057.49,9485.51) 8057.49,9500 cw(c8057.49,9514.49) v3@8047.24,9504.24 ; R45.2@8076.86,9590.32 cw(c8053.5,9566.96) 8086.54,9566.96 cw(c8119.57,9566.96) R45.2@8096.21,9590.32 ; v3@8532.53,9232.99 cw(c8522.29,9222.74) 8536.77,9222.74 cw(c8551.26,9222.74) v3@8541.01,9232.99 ; U13.4@8536.77,9180 v3(8536.77,9237.23)
  BottomLayer w12: v3@8043,9494 cw(c8043,9479.51) 8053.24,9489.76 cw(c8063.49,9500) v3@8049,9500 ; v3(8043,9500) 8305.77,9237.23 v3(8536.77,9237.23) ; v3@8532.53,9232.99 ccw(c8522.29,9222.74) 8522.29,9237.23 ccw(c8522.29,9251.71) v3@8532.53,9241.47
AOE#: R71.6 U1.234 U4.19 | length 2613.1
  TopLayer w6: U1.234@6066.54,7547.22 cw(c6061.58,7542.26) 6068.6,7542.26 cw(c6075.61,7542.26) U1.234@6070.65,7547.22 ; U1.234@6068.6,7585.69 6068.6,7530.6 5938,7400 5938,7160 6034,7064 6561,7064 6603,7022 v1(7366,7022) ; v1@6748.13,6890.13 cw(c6739.6,6881.6) 6751.67,6881.6 cw(c6763.74,6881.6) v1@6755.21,6890.13 ; U4.19@6749.62,6869.52 ccw(c6744.66,6874.48) 6751.67,6874.48 ccw(c6758.68,6874.48) U4.19@6753.72,6869.52 ; U4.19@6751.67,6834 v1(6751.67,6893.67) ; v1@6842.46,7018.46 ccw(c6833.93,7009.93) 6833.93,7022 ccw(c6833.93,7034.07) v1@6842.46,7025.54 ; v1@6849.54,7018.46 cw(c6858.07,7009.93) 6858.07,7022 cw(c6858.07,7034.07) v1@6849.54,7025.54 ; v1@7362.46,7018.46 ccw(c7353.93,7009.93) 7353.93,7022 ccw(c7353.93,7034.07) v1@7362.46,7025.54
  BottomLayer w6: v1@6748.13,6897.21 ccw(c6739.6,6905.74) 6751.67,6905.74 ccw(c6763.74,6905.74) v1@6755.21,6897.21 ; v1(6751.67,6893.67) 6751.67,6948.67 6825,7022 v1(6846,7022) ; v1@6842.46,7018.46 ccw(c6833.93,7009.93) 6833.93,7022 ccw(c6833.93,7034.07) v1@6842.46,7025.54 ; v1(7366,7022) 7466,7122 R71.6@7555.84,7122 ; v1@7366,7027 ccw(c7366,7039.07) 7374.54,7030.54 ccw(c7383.07,7022) v1@7371,7022 ; R71.6@7543.1,7117.76 ccw(c7532.86,7107.51) 7532.86,7122 ccw(c7532.86,7136.49) R71.6@7543.1,7126.24
ARE#: R71.5 U1.233 U2.28 U4.18 | length 3661.3
  TopLayer w6: U2.28@5170.72,6807.7 v1(5223.7,6807.7) ; U2.28@5206.24,6805.65 cw(c5211.2,6800.69) 5211.2,6807.7 cw(c5211.2,6814.71) U2.28@5206.24,6809.75 ; v1@5220.16,6804.16 ccw(c5211.63,6795.63) 5211.63,6807.7 ccw(c5211.63,6819.77) v1@5220.16,6811.24 ; v1@5988,7068 ccw(c5975.93,7068) 5984.46,7076.54 ccw(c5993,7085.07) v1@5993,7073 ; v1@5993,7063 cw(c5993,7050.93) 6001.54,7059.46 cw(c6010.07,7068) v1@5998,7068 ; U1.233@6046.86,7547.22 cw(c6041.9,7542.26) 6048.91,7542.26 cw(c6055.93,7542.26) U1.233@6050.97,7547.22 ; U1.233@6048.91,7572.9 6048.91,7531.91 5922,7405 5922,7139 6017,7044 6546,7044 6587,7003 v1(7393,7003) ; v1@6767.82,6911.82 cw(c6759.28,6903.28) 6771.36,6903.28 cw(c6783.43,6903.28) v1@6774.89,6911.82 ; U4.18@6769.3,6869.52 ccw(c6764.34,6874.48) 6771.36,6874.48 ccw(c6778.37,6874.48) U4.18@6773.41,6869.52 ; U4.18@6771.35,6834 v1(6771.35,6915.35) ; v1@6869.46,6999.46 ccw(c6860.93,6990.93) 6860.93,7003 ccw(c6860.93,7015.07) v1@6869.46,7006.54 ; v1@6876.54,6999.46 cw(c6885.07,6990.93) 6885.07,7003 cw(c6885.07,7015.07) v1@6876.54,7006.54 ; v1@7389.46,6999.46 ccw(c7380.93,6990.93) 7380.93,7003 ccw(c7380.93,7015.07) v1@7389.46,7006.54
  BottomLayer w6: v1(5223.7,6807.7) 5728.7,6807.7 v1(5993,7068) ; v1@5227.24,6804.16 cw(c5235.77,6795.63) 5235.77,6807.7 cw(c5235.77,6819.77) v1@5227.24,6811.24 ; v1@5988,7068.04 cw(c5975.93,7068.13) 5984.4,7059.53 cw(c5992.87,7050.93) v1@5992.96,7063 ; v1@6767.82,6918.89 ccw(c6759.28,6927.43) 6771.36,6927.43 ccw(c6783.43,6927.43) v1@6774.89,6918.89 ; v1(6771.35,6915.35) 6771.35,6947.35 6827,7003 v1(6873,7003) ; v1@6869.46,6999.46 ccw(c6860.93,6990.93) 6860.93,7003 ccw(c6860.93,7015.07) v1@6869.46,7006.54 ; v1(7393,7003) 7476,7086 R71.5@7555.84,7086 ; v1@7393,7008 ccw(c7393,7020.07) 7401.54,7011.54 ccw(c7410.07,7003) v1@7398,7003 ; R71.5@7543.1,7081.76 ccw(c7532.86,7071.51) 7532.86,7086 ccw(c7532.86,7100.49) R71.5@7543.1,7090.24
AS_CONFDN: JP11.3 R26.1 U1.145 | length 3486.3
  TopLayer w6: U1.145@4937.69,8362.27 v1(6221.73,8362.27) ; U1.145@4950.57,8360.21 cw(c4955.53,8355.25) 4955.53,8362.27 cw(c4955.53,8369.28) U1.145@4950.57,8364.32 ; v1@6218.2,8358.73 ccw(c6209.66,8350.2) 6209.66,8362.27 ccw(c6209.66,8374.34) v1@6218.2,8365.8 ; JP11.3@6901.45,7920.97 ccw(c6825.78,8006.53) R26.1@6940,8006.54 6940,7920 JP11.3@6920,7900 ; JP11.3@6905.43,7916.48 ccw(c6837.56,7993.21) R26.1@6940,7993.21 ; JP11.3@6909.4,7911.99 ccw(c6849.34,7979.9) 6940,7979.9 ; JP11.3@6913.38,7907.49 ccw(c6861.11,7966.58) 6940,7966.58 ; JP11.3@6917.35,7903 ccw(c6872.89,7953.27) 6940,7953.27 ; JP11.3@6921.32,7898.5 ccw(c6884.67,7939.95) 6940,7939.95 ; JP11.3@6925.3,7894.01 ccw(c6896.45,7926.63) 6940,7926.63 ; R26.1@6928.2,7992.77 cw(c6899.72,7964.29) 6940,7964.29 cw(c6980.28,7964.29) R26.1@6951.8,7992.77 ; R26.1@6932.44,7997.01 cw(c6914.2,7978.77) 6940,7978.77 cw(c6965.8,7978.77) R26.1@6947.56,7997.01
  BottomLayer w6: v1@6221.73,8357.27 cw(c6221.73,8345.2) 6230.27,8353.73 cw(c6238.8,8362.27) v1@6226.73,8362.27 ; v1(6221.73,8362.27) 6554,8030 6554,7777 6589,7742 6844,7742 6870,7768 6870,7850 JP11.3@6920,7900 ; JP11.3@6892,7900 cw(c6824.4,7900) 6872.2,7852.2 cw(c6920,7804.4) JP11.3@6920,7872 ; JP11.3@6898,7900 cw(c6844.89,7900) 6882.44,7862.44 cw(c6920,7824.89) JP11.3@6920,7878 ; JP11.3@6904,7900 cw(c6865.37,7900) 6892.69,7872.69 cw(c6920,7845.37) JP11.3@6920,7884
AS_DCLK: JP11.1 U1.36 U19.6 | length 1418.3
  TopLayer w6: U1.36@6274.31,8362.27 6275.57,8361 v1(6341,8361) ; U1.36@6312.78,8364.32 ccw(c6320.8,8372.34) 6320.8,8361 ; v1@6337.46,8357.46 ccw(c6328.93,8348.93) 6328.93,8361 ccw(c6328.93,8373.07) v1@6337.46,8364.54
  BottomLayer w6: v1@6341,8356 cw(c6341,8343.93) 6349.54,8352.46 cw(c6358.07,8361) v1@6346,8361 ; v1(6341,8361) 6400,8302 6729,8302 6755,8276 6755,8163 6794,8124 6883,8124 7020,7987 JP11.1@7020,7900 ; U19.6@6748.77,8184.64 cw(c6733.73,8169.59) 6755,8169.59 cw(c6776.27,8169.59) U19.6@6761.23,8184.64 ; U19.6@6748.77,8260.09 ccw(c6733.73,8275.13) 6755,8275.13 ccw(c6776.27,8275.13) U19.6@6761.23,8260.09 ; JP11.1@7000.2,7919.8 ccw(c6952.4,7967.6) 7020,7967.6 ccw(c7087.6,7967.6) JP11.1@7039.8,7919.8 ; JP11.1@7004.44,7915.56 ccw(c6966.89,7953.11) 7020,7953.11 ccw(c7073.11,7953.11) JP11.1@7035.56,7915.56 ; JP11.1@7008.69,7911.31 ccw(c6981.37,7938.63) 7020,7938.63 ccw(c7058.63,7938.63) JP11.1@7031.31,7911.31
AS_NCONFIG: JP11.5 R24.1 U1.26 | length 1364.8
  TopLayer w6: U1.26@6287.1,8165.42 6553.58,8165.42 6819,7900 JP11.5@6820,7900 R24.1@6820,8006.54 ; U1.26@6312.78,8163.36 cw(c6317.74,8158.4) 6317.74,8165.42 cw(c6317.74,8172.43) U1.26@6312.78,8167.47 ; 6770.49,7948.51 ccw(c6820,7998.01) JP11.5@6820,7928 ; 6772.91,7946.09 cw(c6726.82,7900) JP11.5@6792,7900 ; 6780.74,7938.26 ccw(c6820,7977.53) JP11.5@6820,7922 ; 6783.15,7935.85 cw(c6747.3,7900) JP11.5@6798,7900 ; 6790.98,7928.02 ccw(c6820,7957.04) JP11.5@6820,7916 ; 6793.39,7925.61 cw(c6767.79,7900) JP11.5@6804,7900 ; JP11.5@6800.2,7919.8 ccw(c6752.4,7967.6) 6820,7967.6 ccw(c6887.6,7967.6) JP11.5@6839.8,7919.8 ; JP11.5@6804.44,7915.56 ccw(c6766.89,7953.11) 6820,7953.11 ccw(c6873.11,7953.11) JP11.5@6835.56,7915.56 ; R24.1@6808.2,7992.77 cw(c6779.72,7964.29) 6820,7964.29 cw(c6860.28,7964.29) R24.1@6831.8,7992.77 ; JP11.5@6808.69,7911.31 ccw(c6781.37,7938.63) 6820,7938.63 ccw(c6858.63,7938.63) JP11.5@6831.31,7911.31 ; R24.1@6812.44,7997.01 cw(c6794.2,7978.77) 6820,7978.77 cw(c6845.8,7978.77) R24.1@6827.56,7997.01
AWE#: R34.7 U1.236 U2.11 U4.17 | length 3460.5
  TopLayer w6: v1(5904.15,6610.85) U2.11@5966,6610.85 ; v1@5907.69,6607.31 cw(c5916.22,6598.78) 5916.22,6610.85 cw(c5916.22,6622.92) v1@5907.69,6614.39 ; U2.11@5930.48,6608.8 ccw(c5925.52,6603.84) 5925.52,6610.85 ccw(c5925.52,6617.86) U2.11@5930.48,6612.9 ; U1.236@6105.91,7547.22 cw(c6100.95,7542.26) 6107.97,7542.26 cw(c6114.98,7542.26) U1.236@6110.02,7547.22 ; U1.236@6107.97,7585.69 6107.97,7525.97 5969,7387 5969,7180 6036,7113 6595,7113 6619,7089 7543.84,7089 R34.7@7555.84,7077 ; v1@6173.46,7109.46 ccw(c6164.93,7100.93) 6164.93,7113 ccw(c6164.93,7125.07) v1@6173.46,7116.54 ; v1@6180.54,7109.46 cw(c6189.07,7100.93) 6189.07,7113 cw(c6189.07,7125.07) v1@6180.54,7116.54 ; v1@6787.5,6887.5 cw(c6778.97,6878.97) 6791.04,6878.97 cw(c6803.11,6878.97) v1@6794.58,6887.5 ; U4.17@6788.99,6869.52 ccw(c6784.03,6874.48) 6791.04,6874.48 ccw(c6798.05,6874.48) U4.17@6793.09,6869.52 ; U4.17@6791.04,6834 v1(6791.04,6891.04) ; v1@6985.46,7085.46 ccw(c6976.93,7076.93) 6976.93,7089 ccw(c6976.93,7101.07) v1@6985.46,7092.54 ; v1@6992.54,7085.46 cw(c7001.07,7076.93) 7001.07,7089 cw(c7001.07,7101.07) v1@6992.54,7092.54 ; 7503.89,7089 cw(c7503.89,7033.54) R34.7@7543.1,7072.76 ; 7518.37,7089 cw(c7518.37,7048.03) 7547.34,7077 ccw(c7539.22,7080.89) 7545.59,7087.26 ; 7532.86,7089 cw(c7532.86,7062.51) R34.7@7551.59,7081.24
  BottomLayer w6: v1@5900.61,6614.39 ccw(c5892.08,6622.92) 5904.15,6622.92 ccw(c5916.22,6622.92) v1@5907.69,6614.39 ; v1(5904.15,6610.85) 5904.15,6840.15 v1(6177,7113) ; v1@6172,7113 cw(c6159.93,7113) 6168.46,7104.46 cw(c6177,7095.93) v1@6177,7108 ; v1@6787.5,6894.58 ccw(c6778.97,6903.11) 6791.04,6903.11 ccw(c6803.11,6903.11) v1@6794.58,6894.58 ; v1(6791.04,6891.04) 6791.04,6931.04 6838.94,6978.94 6878.94,6978.94 v1(6989,7089) ; v1@6984,7089 cw(c6971.93,7089) 6980.46,7080.46 cw(c6989,7071.93) v1@6989,7084
BE0#: R72.5 U1.227 U4.16 | length 2600.1
  TopLayer w6: U1.227@5928.75,7547.22 cw(c5923.79,7542.26) 5930.8,7542.26 cw(c5937.82,7542.26) U1.227@5932.86,7547.22 ; U1.227@5930.8,7585.69 5930.8,7468.8 5869,7407 5869,7089 5960,6998 6501,6998 6559,6940 6780.45,6940 v1(6810.73,6909.73) U4.16@6810.73,6834 ; v1@6805.73,6909.73 ccw(c6793.65,6909.73) 6802.19,6918.26 ccw(c6810.73,6926.8) v1@6810.73,6914.72 ; v1@6807.19,6906.19 cw(c6798.65,6897.65) 6810.73,6897.65 cw(c6822.8,6897.65) v1@6814.26,6906.19 ; U4.16@6808.67,6869.52 ccw(c6803.71,6874.48) 6810.73,6874.48 ccw(c6817.74,6874.48) U4.16@6812.78,6869.52
  BottomLayer w6: v1(6810.73,6909.73) 6859,6958 6898,6958 7186,7246 R72.5@7555.84,7246 ; v1@6810.73,6914.72 ccw(c6810.73,6926.8) 6819.26,6918.26 ccw(c6827.8,6909.73) v1@6815.72,6909.73 ; R72.5@7543.1,7241.76 ccw(c7532.86,7231.51) 7532.86,7246 ccw(c7532.86,7260.49) R72.5@7543.1,7250.24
